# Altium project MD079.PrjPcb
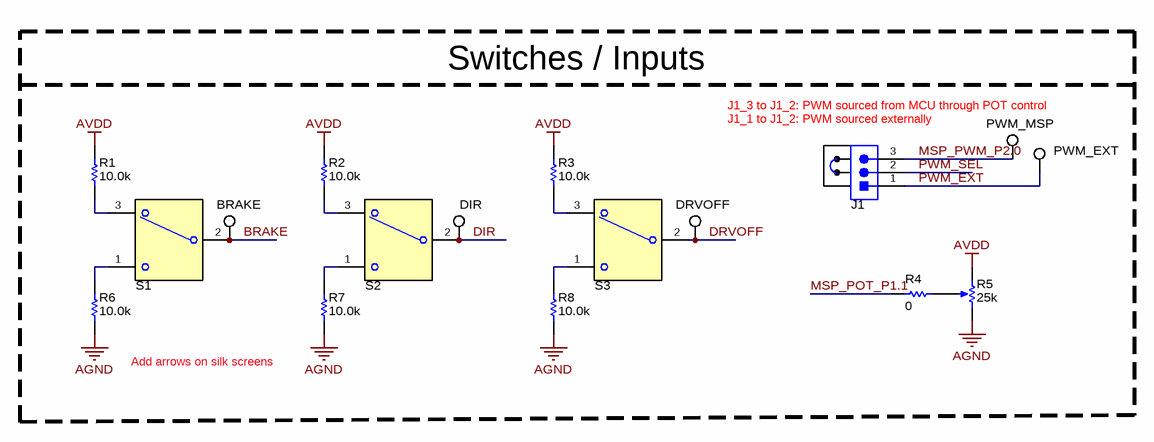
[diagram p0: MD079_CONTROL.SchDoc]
CopyrightYear: 2023; PCB_Layout: Hong Ze Khor; PCB_Rev: A; PRJ_Customer: Public Release; PRJ_Engineer: Hong Ze Khor; PRJ_Number: MD079; PRJ_Title: MCT8315ZEVM; ProjectVariant: EVM_Orderable; SCH_Rev: A; TechSupport: http://www.ti.com/support; TID: N/A
5 sheets, 172 parts. Net scope: global (net labels, ports and power ports of the same name join across sheets).
Board file: MD079.PcbDoc
Sheets:
  MD079_CONTROL.SchDoc
  MD079_DRIVER.SchDoc
  MD079_HARDWARE.SchDoc
  MD079_INTERFACE.SchDoc
  MD079_POWER_AND_CONNECTORS.SchDoc

## Sheet MD079_CONTROL.SchDoc
size 431 x 279 mm; Date: Not shown in title block; ApprovedBy: Not shown in title block; CheckedBy: Not shown in title block; Author: Not shown in title block; CompanyName: Not shown in title block; Engineer: Not shown in title block; Organization: Not shown in title block; Address1: Not shown in title block; Address2: Not shown in title block; Address3: Not shown in title block; Address4: Not shown in title block; DocumentNumber: 1; Revision: Use project parameter SCH_Rev; SheetNumber: 2; SheetTotal: 5; PageSetup: Record=PageOptions¦CenterHorizontal=True¦CenterVertical=True¦PrintScale=1.00¦XCorrection=1.00¦YCorrection=1.00¦PrintKind=0¦BorderSize=5000000¦LeftOffset=0¦BottomOffset=0¦Orientation=2¦PaperLength=1000¦PaperWidth=1000¦Scale=100¦PaperSource=15¦PrintQuality=600¦MediaType=1¦DitherType=10¦PaperKind=Letter¦PrintScaleMode=1

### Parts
J1  Header_3x1  [PBC03SAAN]  (value not drawn)
R1  ValueDisplayed: 10.0k  [0603]  (hidden comment: RC0603FR-0710KL)
R2  ValueDisplayed: 10.0k  [0603]  (hidden comment: RC0603FR-0710KL)
R3  ValueDisplayed: 10.0k  [0603]  (hidden comment: RC0603FR-0710KL)
R4  ValueDisplayed: 0  [0603L]  (hidden comment: ERJ-3GEY0R00V)
R5  value 25k  [Bourns_3352T]  (hidden comment: 3352T-1-253LF)
R6  ValueDisplayed: 10.0k  [0603]  (hidden comment: RC0603FR-0710KL)
R7  ValueDisplayed: 10.0k  [0603]  (hidden comment: RC0603FR-0710KL)
R8  ValueDisplayed: 10.0k  [0603]  (hidden comment: RC0603FR-0710KL)
S1  SW_SPDT_COM2_1_3  [SW_B12AP]  (value not drawn)
S2  SW_SPDT_COM2_1_3  [SW_B12AP]  (value not drawn)
S3  SW_SPDT_COM2_1_3  [SW_B12AP]  (value not drawn)
SH-J1  SNT-100-BK-G  [SNT-100-BK-G]  (value not drawn)
TP1  PWM_MSP  [Keystone5002]
TP2  PWM_EXT  [Keystone5002]
TP3  BRAKE  [Keystone5002]
TP4  DIR  [Keystone5002]
TP5  DRVOFF  [Keystone5002]

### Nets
AGND: R5.3(CW) R6.1 R7.1 R8.1
AVDD: R1.2 R2.2 R3.2 R5.1(CCW)
BRAKE: S1.2(COM) TP3.1
DIR: S2.2(COM) TP4.1
DRVOFF: S3.2(COM) TP5.1
MSP_POT_P1.1: R4.1
MSP_PWM_P2.0: J1.3 TP1.1
PWM_EXT: J1.1 TP2.1
PWM_SEL: J1.2
NetR1_1: R1.1 S1.3
NetR2_1: R2.1 S2.3
NetR3_1: R3.1 S3.3
NetR4_2: R4.2 R5.2(WIPER)
NetR6_2: R6.2 S1.1
NetR7_2: R7.2 S2.1
NetR8_2: R8.2 S3.1

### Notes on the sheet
- Switches / Inputs
- J1_1 to J1_2: PWM sourced externally
- J1_3 to J1_2: PWM sourced from MCU through POT control
- Add arrows on silk screens

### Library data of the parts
J1 = CMP-0002334-1: Header, 100mil, 3x1, Gold, TH; Manufacturer: Sullins Connector Solutions; CNHeader: TRUE; CT: FALSE; Green_Lifecycle: Not Set; Green_REACh: Incomplete
R1-R3 R6-R8 = CMP-0022746-5: RES, 10.0 k, 1%, 0.1 W, 0603; Manufacturer: Yageo; Power_W: 100mW; TempCo: 100 ppm/C; Value_Code: 10k0; Value: 10.0k; EIA_Code: E96; Res_ohm: 10k; SizeX_mm: 1.6; SizeY_mm: 0.8; SizeZ_mm: 1; Value2: 0.1W; SizeArea_mm2: 1.28; AEC Qualified: N; VDC_V: 75V; AEC Category: Q200; SizeAreaWB_mm2: 4.68
R4 = CMP-0025874-4: RES, 0, 5%, 0.1 W, AEC-Q200 Grade 0, 0603; Manufacturer: Panasonic; Power_W: 100mW; TempCo: 600 ppm/C; Value_Code: 0000; Value: 0; EIA_Code: E24; SizeX_mm: 1.6; SizeY_mm: 0.8; SizeZ_mm: 1; Value2: 0.1W; SizeArea_mm2: 1.28; AEC Qualified: Y; VDC_V: 50V; AEC Category: Q200; SizeAreaWB_mm2: 4.68
R5 = CMP-0001776-2: Trimmer Potentiometer, 25kohm, 0.5W, TH; Manufacturer: Bourns
S1-S3 = CMP-0002155-2: SWITCH TOGGLE SPDT 0.4VA 28V; PartNumber: B12AP; Manufacturer: NKK Switches; SwitchFunction: On-On; PositionCount: 2; CurrentRating_mA: 100A
SH-J1 = CMP-0003623-3: Shunt, 100mil, Gold plated, Black; Alternate PartNumber: 969102-0000-DA; Manufacturer: Samtec; Alternate Manufacturer: 3M; Value: 1x2
TP1-TP5 = CMP-0055139-2: Test Point, Miniature, White, TH; Manufacturer: Keystone Electronics; CNHeader: FALSE; Green_Lifecycle: Active; Green_REACh: Passed; ContactFinish: Silver; CT: TRUE

## Sheet MD079_DRIVER.SchDoc
size 431 x 279 mm; Date: Not shown in title block; ApprovedBy: Not shown in title block; CheckedBy: Not shown in title block; Author: Not shown in title block; CompanyName: Not shown in title block; Engineer: Not shown in title block; Organization: Not shown in title block; Address1: Not shown in title block; Address2: Not shown in title block; Address3: Not shown in title block; Address4: Not shown in title block; DocumentNumber: 2; Revision: Use project parameter SCH_Rev; SheetNumber: 3; SheetTotal: 5; PageSetup: Record=PageOptions¦CenterHorizontal=True¦CenterVertical=True¦PrintScale=1.00¦XCorrection=1.00¦YCorrection=1.00¦PrintKind=0¦BorderSize=5000000¦LeftOffset=0¦BottomOffset=0¦Orientation=2¦PaperLength=1000¦PaperWidth=1000¦Scale=100¦PaperSource=15¦PrintQuality=600¦MediaType=1¦DitherType=10¦PaperKind=Letter¦PrintScaleMode=1
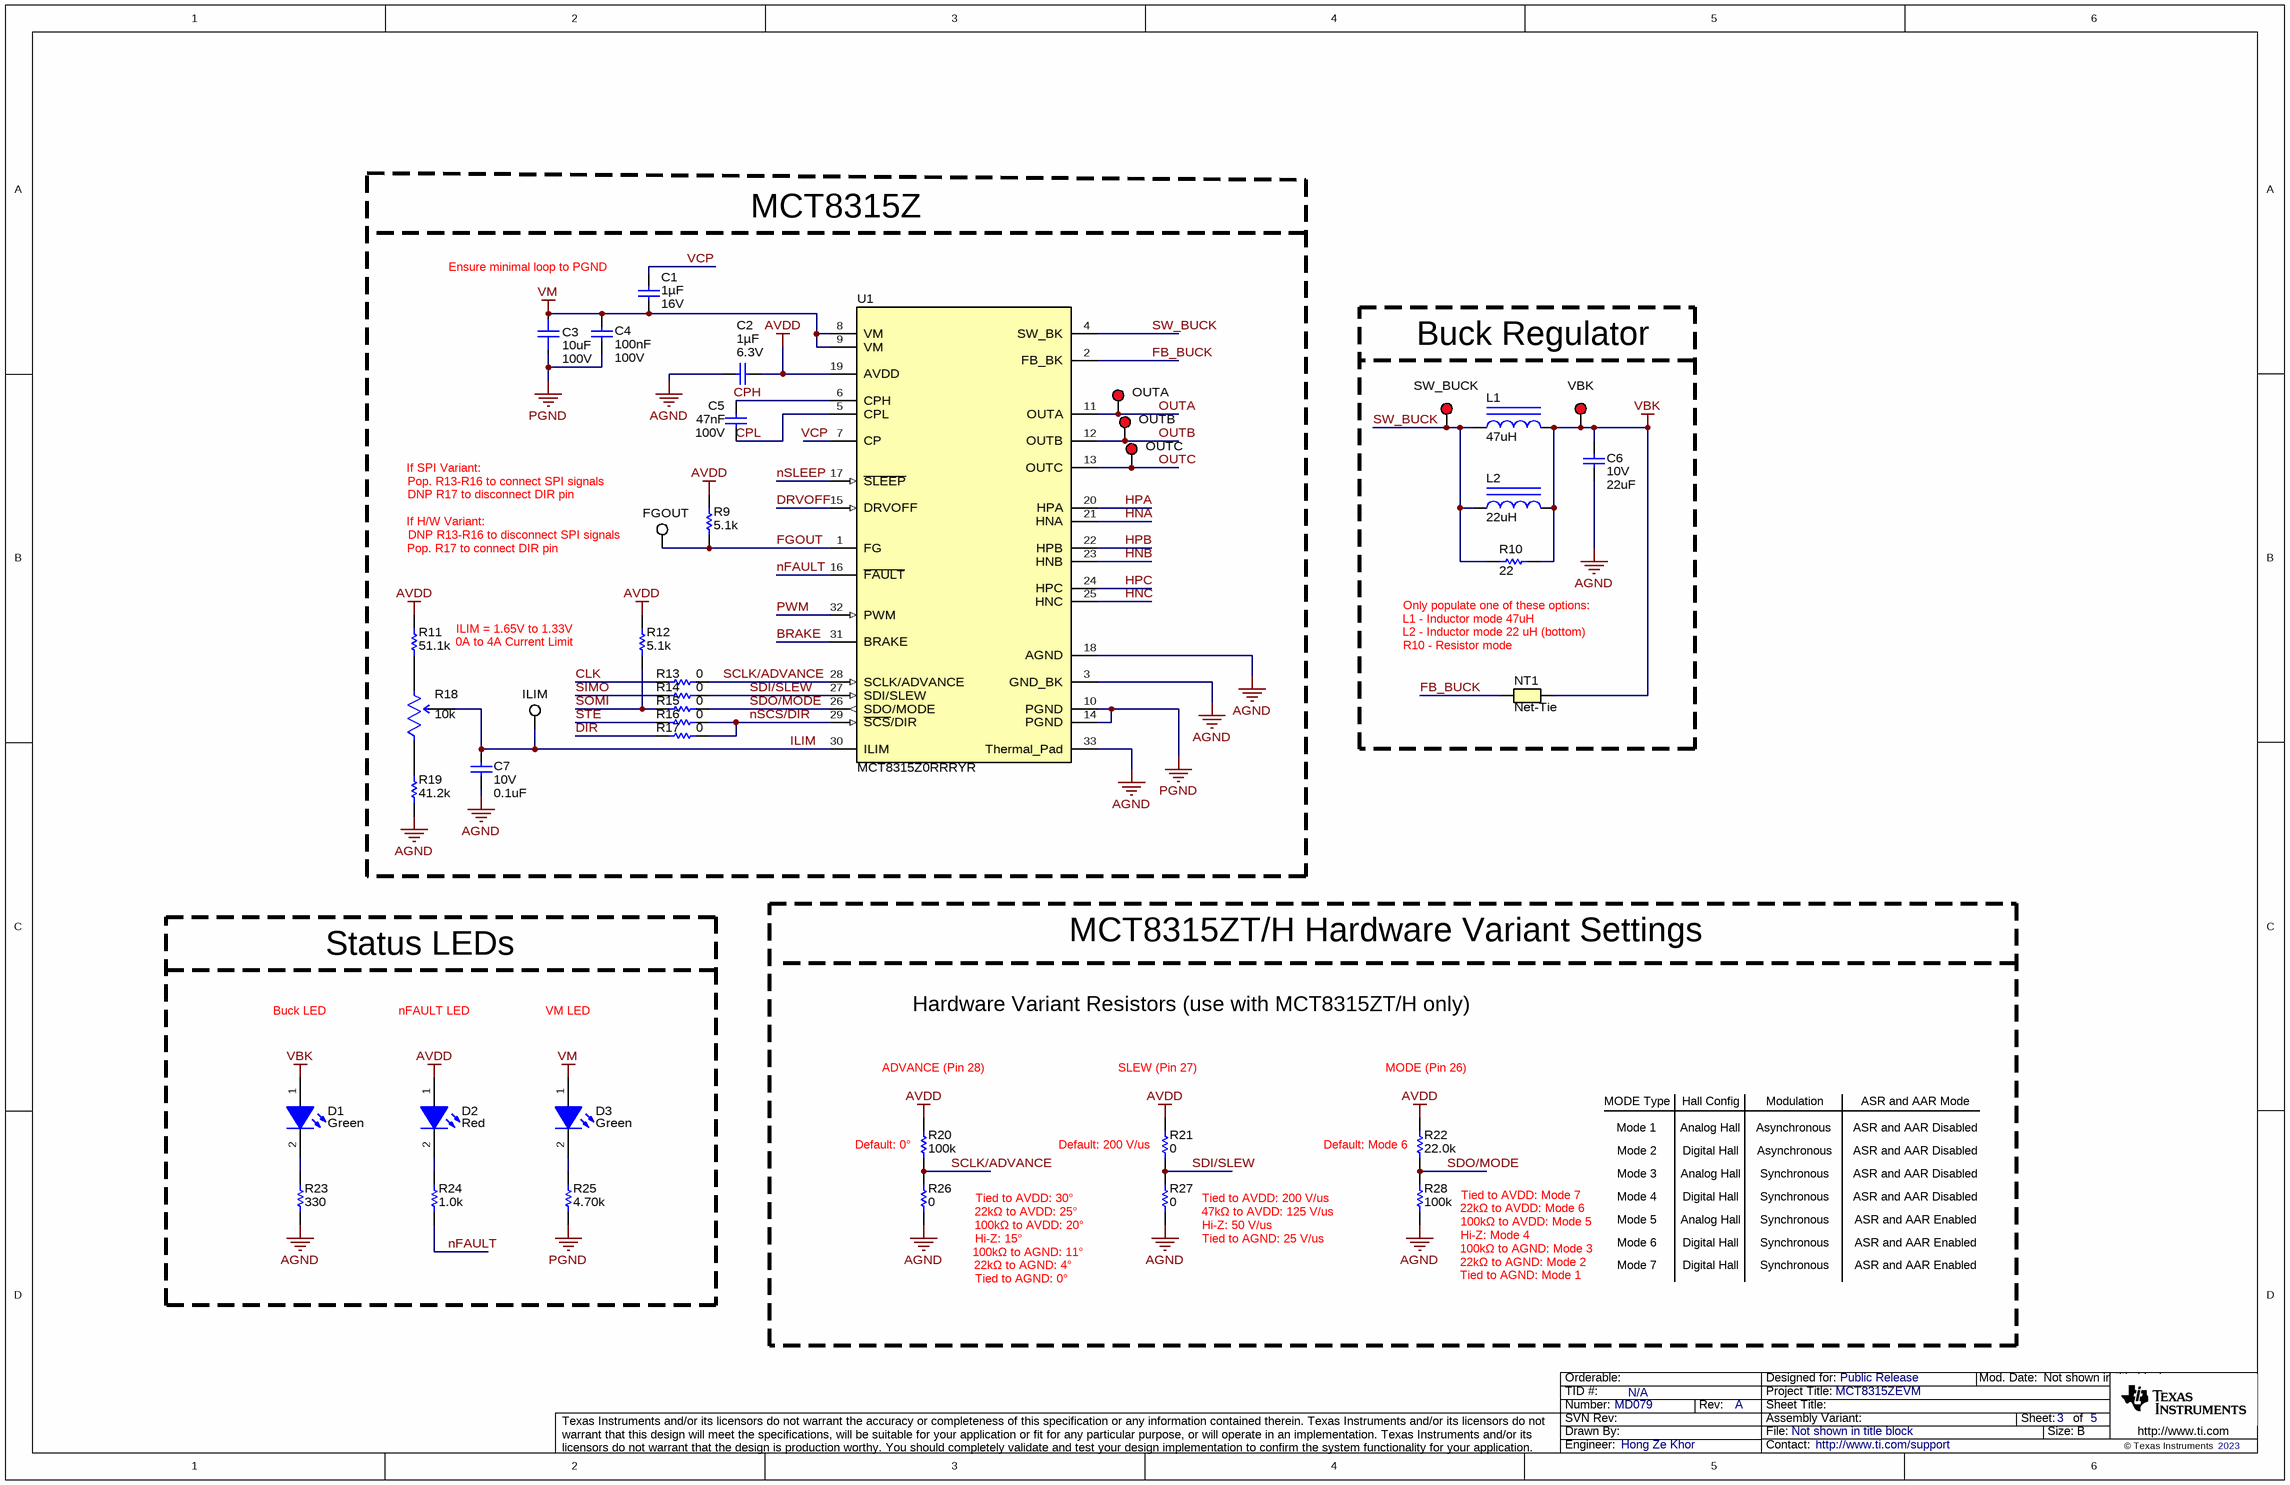
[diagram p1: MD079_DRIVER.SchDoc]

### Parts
C1  ValueDisplayed: 1µF  VDC_V: 16V  [0603]  (hidden comment: 0603YD105KAT2A)
C2  Cap_F: 1µF  VDC_V: 6.3V  [0603L]  (hidden comment: C0603C105K9RACAUTO)
C3  ValueDisplayed: 10uF  VDC_V: 100V  [FP-C3216X6S2A106K160AC_1206-MFG]  (hidden comment: C3216X6S2A106K160AC)
C4  Cap_F: 100nF  VDC_V: 100V  [0603]  (hidden comment: GCJ188R72A104KA01D)
C5  Cap_F: 47nF  VDC_V: 100V  [0805_HV]  (hidden comment: C2012X7R2A473K125AA)
C6  VDC_V: 10V  ValueDisplayed: 22uF  [1206_180L]  (hidden comment: GRM31CR71A226KE15L)
C7  VDC_V: 10V  ValueDisplayed: 0.1uF  [0402]  (hidden comment: C1005X5R1A104K050BA)
D1  value Green  [LTST-C170KGKT_Green]  (hidden comment: LTST-C170KGKT)
D2  value Red  [LED_LTST-C170_Red]  (hidden comment: LTST-C170KRKT)
D3  value Green  [LTST-C170KGKT_Green]  (hidden comment: LTST-C170KGKT)
L1  ValueDisplayed: 47uH  [WE-MAIA_3015]  (hidden comment: 78438335470)
L2  ValueDisplayed: 22uH  [WE-MAIA_3015]  (hidden comment: 78438335220)
NT1  Net-Tie  [Net-Tie_10mil]  (net tie, no BOM)
R9  ValueDisplayed: 5.1k  [0603L]  (hidden comment: CRCW06035K10JNEA)
R10  ValueDisplayed: 22  [2512]  (hidden comment: CRCW251222R0JNEGHP)
R11  ValueDisplayed: 51.1k  [0603]  (hidden comment: RC0603FR-0751K1L)
R12  ValueDisplayed: 5.1k  [0603L]  (hidden comment: CRCW06035K10JNEA)
R13  ValueDisplayed: 0  [0603L]  (hidden comment: ERJ-3GEY0R00V)
R14  ValueDisplayed: 0  [0603L]  (hidden comment: ERJ-3GEY0R00V)
R15  ValueDisplayed: 0  [0603L]  (hidden comment: ERJ-3GEY0R00V)
R16  ValueDisplayed: 0  [0603L]  (hidden comment: ERJ-3GEY0R00V)
R17  ValueDisplayed: 0  [0603L]  (hidden comment: ERJ-3GEY0R00V)
R18  value 10k  [Bourns_3352T]  (hidden comment: 3352T-1-103LF)
R19  ValueDisplayed: 41.2k  [0603]  (hidden comment: RC0603FR-0741K2L)
R20  ValueDisplayed: 100k  [0603L]  (hidden comment: ERA-3AEB104V)
R21  ValueDisplayed: 0  [0603L]  (hidden comment: ERJ-3GEY0R00V)
R22  ValueDisplayed: 22.0k  [0603L]  (hidden comment: ERJ-3EKF2202V)
R23  ValueDisplayed: 330  [0603L]  (hidden comment: RC0603FR-07330RL)
R24  ValueDisplayed: 1.0k  [0603L]  (hidden comment: RC0603JR-071KL)
R25  ValueDisplayed: 4.70k  [0603L]  (hidden comment: RT0603BRD074K7L)
R26  ValueDisplayed: 0  [0603L]  (hidden comment: ERJ-3GEY0R00V)
R27  ValueDisplayed: 0  [0603L]  (hidden comment: ERJ-3GEY0R00V)
R28  ValueDisplayed: 100k  [0603L]  (hidden comment: ERA-3AEB104V)
TP6  OUTA  [Keystone5000]
TP7  SW_BUCK  [Keystone5000]
TP8  VBK  [Keystone5000]
TP9  OUTB  [Keystone5000]
TP10  OUTC  [Keystone5000]
TP11  FGOUT  [Keystone5002]
TP12  ILIM  [Keystone5002]
U1  MCT8315Z0RRRYR  [RRY0032A-MFG]

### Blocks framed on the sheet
MCT8315Z: C1-C5 C7 R9 R11-R19 TP6 TP9-TP12 U1
Buck Regulator: C6 L1 L2 NT1 R10 TP7 TP8
MCT8315ZT/H Hardware Variant Settings: R20-R22 R26-R28
Status LEDs: D1-D3 R23-R25

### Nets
AGND: C2.1 C6.2 C7.2 R19.1 R23.1 R26.1 R27.1 R28.1 U1.3(GND_BK) U1.18(AGND) U1.33(Thermal_Pad)
AVDD: C2.2 D2.1(A) R9.2 R11.2 R12.2 R20.2 R21.2 R22.2 U1.19(AVDD)
PGND: C3.1 C4.2 R25.1 U1.10(PGND) U1.14(PGND)
VBK: C6.1 D1.1(A) L1.2 L2.2 NT1.2 R10.2 TP8.1
VM: C1.2 C3.2 C4.1 D3.1(A) U1.8(VM) U1.9(VM)
BRAKE: U1.31(BRAKE)
CLK: R13.1
CPH: C5.1 U1.6(CPH)
CPL: C5.2 U1.5(CPL)
DIR: R17.1
DRVOFF: U1.15(DRVOFF)
FB_BUCK: NT1.1 U1.2(FB_BK)
FGOUT: R9.1 TP11.1 U1.1(FG)
HNA: U1.21(HNA)
HNB: U1.23(HNB)
HNC: U1.25(HNC)
HPA: U1.20(HPA)
HPB: U1.22(HPB)
HPC: U1.24(HPC)
ILIM: C7.1 R18.2(WIPER) TP12.1 U1.30(ILIM)
nFAULT: R24.1 U1.16(~{FAULT})
nSCS/DIR: R16.2 R17.2 U1.29(~{SCS}/DIR)
nSLEEP: U1.17(~{SLEEP})
OUTA: TP6.1 U1.11(OUTA)
OUTB: TP9.1 U1.12(OUTB)
OUTC: TP10.1 U1.13(OUTC)
PWM: U1.32(PWM)
SCLK/ADVANCE: R13.2 R20.1 R26.2 U1.28(SCLK/ADVANCE)
SDI/SLEW: R14.2 R21.1 R27.2 U1.27(SDI/SLEW)
SDO/MODE: R15.2 R22.1 R28.2 U1.26(SDO/MODE)
SIMO: R14.1
SOMI: R12.1 R15.1
STE: R16.1
SW_BUCK: L1.1 L2.1 R10.1 TP7.1 U1.4(SW_BK)
VCP: C1.1 U1.7(CP)
NetD1_2: D1.2(K) R23.2
NetD2_2: D2.2(K) R24.2
NetD3_2: D3.2(K) R25.2
NetR11_1: R11.1 R18.3(CW)
NetR18_1: R18.1(CCW) R19.2

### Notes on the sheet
- Ensure minimal loop to PGND
- If SPI Variant:
- DNP R17 to disconnect DIR pin
- Pop. R13-R16 to connect SPI signals
- If H/W Variant:
- Pop. R17 to connect DIR pin
- (near TP11) DNP R13-R16 to disconnect SPI signals
- (near R11) ILIM = 1.65V to 1.33V
- L1 - Inductor mode 47uH
- L2 - Inductor mode 22 uH (bottom)
- (near R10) Only populate one of these options:
- 0A to 4A Current Limit
- (near NT1) R10 - Resistor mode
- Buck LED
- nFAULT LED
- VM LED
- Hardware Variant Resistors (use with MCT8315ZT/H only)
- ADVANCE (Pin 28)
- SLEW (Pin 27)
- MODE (Pin 26)
- MODE Type
- Hall Config
- Modulation
- ASR and AAR Mode
- (near R20) Default: 0°
- (near R21) Default: 200 V/us
- (near R22) Default: Mode 6
- Mode 1
- Mode 2
- Mode 3
- Analog Hall
- Digital Hall
- Asynchronous
- Synchronous
- ASR and AAR Disabled
- (near R26) Hi-Z: 15°
- Tied to AVDD: 30°
- 22kΩ to AVDD: 25°
- 100kΩ to AVDD: 20°
- (near R27) Hi-Z: 50 V/us
- (near R27) Tied to AGND: 25 V/us
- Tied to AVDD: 200 V/us
- (near R27) 47kΩ to AVDD: 125 V/us
- (near R28) Hi-Z: Mode 4
- Tied to AVDD: Mode 7
- 22kΩ to AVDD: Mode 6
- (near R28) 100kΩ to AVDD: Mode 5
- Mode 4
- Mode 6
- Mode 5
- ASR and AAR Enabled
- Tied to AGND: 0°
- 22kΩ to AGND: 4°
- 100kΩ to AGND: 11°
- Tied to AGND: Mode 1
- 22kΩ to AGND: Mode 2
- 100kΩ to AGND: Mode 3
- Mode 7

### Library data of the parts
C1 = CMP-0860183-1: CAP, CERM, 1 µF, 16 V,+/- 10%, X5R, 0603; Manufacturer: AVX; SizeArea_mm2: 1.28; U/M: EA; TaMax_C: 85°C; Polarized: N; Value: 1uF; AEC Category: Q200; SizeX_mm: 1.6; SizeAreaWB_mm2: 4.68; TaMin_C: -55°C; SizeZ_mm: 1; SizeY_mm: 0.8
C2 = CMP-0086190-1: CAP, CERM, 1 µF, 6.3 V,+/- 10%, X7R, AEC-Q200 Grade 1, 0603; Manufacturer: Kemet; SizeArea_mm2: 1.28; Cap_Case: 0603; SizeY_mm: 0.8; AEC Category: Q200; AEC Qualified: Y; TaMax_C: 125°C; SizeZ_mm: 1; SizeX_mm: 1.6; Polarized: N; Value: 1uF; SizeAreaWB_mm2: 4.68; TaMin_C: -55°C; U/M: EA
C3 = CMP-0098402-1: 10 µF ±10% 100V Ceramic Capacitor X6S 1206 (3216 Metric); Manufacturer: TDK; AEC Qualified: No; Cap_F: 10µF; SizeZ_mm: 1.9mm; TempCo: 22%; Value: 10µF
C4 = CMP-0064935-4: CAP, CERM, 0.1 uF, 100 V,+/- 10%, X7R, AEC-Q200 Grade 1, 0603; Manufacturer: MuRata; TaMin_C: -55°C; Polarized: N; SizeAreaWB_mm2: 4.68; Value1: Unknown; U/M: EA; Value: 0.1uF; TaMax_C: 125°C; SizeZ_mm: 1; SizeX_mm: 1.6; SizeY_mm: 0.8; SizeArea_mm2: 1.28; AEC Qualified: Y; AEC Category: Q200
C5 = CMP-0007887-2: CAP, CERM, 0.047 uF, 100 V, +/- 10%, X7R, 0805; Manufacturer: TDK; TaMin_C: -55°C; ESR_ohm: 0.049089; Polarized: N; SizeAreaWB_mm2: 6.75; Value1: 0.049089 ohm; U/M: EA; TaMax_C: 125°C; SizeZ_mm: 1.45; SizeX_mm: 2; SizeY_mm: 1.25; Cap_Case: 0805; SizeArea_mm2: 2.5; IRMS_A: 9.63171dA; AEC Category: Q200
C6 = CMP-0008959-2: CAP, CERM, 22 uF, 10 V, +/- 10%, X7R, 1206; Manufacturer: MuRata; TaMin_C: -55°C; Polarized: N; SizeAreaWB_mm2: 10.92; Value1: Unknown; U/M: EA; Value: 22uF; TaMax_C: 125°C; SizeZ_mm: 1.8; SizeX_mm: 3.2; SizeY_mm: 1.6; Cap_Case: 1206; SizeArea_mm2: 5.12; Cap_F: 22µF; AEC Category: Q200
C7 = CMP-0006259-2: CAP, CERM, 0.1 uF, 10 V, +/- 10%, X5R, 0402; Manufacturer: TDK; TaMin_C: -55°C; Polarized: N; SizeAreaWB_mm2: 3; Value1: Unknown; U/M: EA; Value: 0.1uF; TaMax_C: 85°C; SizeZ_mm: 0.6; SizeX_mm: 1; SizeY_mm: 0.5; Cap_F: 100nF; AEC Category: Q200
D1 D3 = CMP-0002888-2: LED, Green, SMD; Manufacturer: Lite-On; Io_A: 20mA; Value1: W; Vf_V: 2V; Type: AlInGaP
D2 = CMP-0002829-3: LED, Red, SMD; Manufacturer: Lite-On; Io_A: 20mA; SizeAreaWB_mm2: 6.75; Value1: W; SizeZ_mm: 1.2; SizeX_mm: 2; SizeY_mm: 1.25; Vf_V: 2V; SizeArea_mm2: 2.5; Type: AlInGaP
L1 = CMP-0064683-2: Inductor, Shielded, Powdered Iron, 47 uH, 0.39 A, 2.3 ohm, AEC-Q200 Grade 1, SMD; Manufacturer: Wurth Elektronik; Isat: 1.18A @ 20% inductance drop; Irms: 0.39A @ 40C rise; SizeAreaWB_mm2: 16; DCR_ohm: 2.3; Value1: 2.3 ohm; Value: 47uH; Imax_A: 390mA; SizeZ_mm: 1.5; SizeX_mm: 3; Value2: 0.39A; SizeArea_mm2: 9; Ind_H: 47µH; AEC Qualified: Y; AEC Grade: 1; AEC Category: Q200
L2 = CMP-0064681-2: Inductor, Shielded, Powdered Iron, 22 uH, 0.6 A, 1.04 ohm, AEC-Q200 Grade 1, SMD; Manufacturer: Wurth Elektronik; Isat: 1.6A @ 20% inductance drop; Irms: 0.6A @ 40C rise; SizeAreaWB_mm2: 16; DCR_ohm: 1.04; Value: 22uH; Imax_A: 600mA; SizeZ_mm: 1.5; SizeX_mm: 3; Value2: 0.6A; SizeArea_mm2: 9; Ind_H: 22µH; AEC Qualified: Y; AEC Grade: 1; AEC Category: Q200
NT1 = CMP-0078142-6: Single point connection between nets.
R9 R12 = CMP-0025830-4: RES, 5.1 k, 5%, 0.1 W, AEC-Q200 Grade 0, 0603; Manufacturer: Vishay-Dale; Power_W: 100mW; TempCo: 200 ppm/C; Value_Code: 5k10; Value: 5.1k; EIA_Code: E24; SizeX_mm: 1.6; SizeY_mm: 0.8; SizeZ_mm: 1; Value2: 0.1W; SizeArea_mm2: 1.28; AEC Qualified: Y; VDC_V: 75V; AEC Category: Q200; AEC Grade: 0
R10 = CMP-0015919-3: RES, 22, 5%, 1.5 W, AEC-Q200 Grade 0, 2512; Manufacturer: Vishay-Dale; Power_W: 1.5W; TempCo: 200 ppm/C; Value_Code: 22R0; Value: 22; EIA_Code: E24; SizeX_mm: 6.3; SizeY_mm: 3.2; SizeZ_mm: 0.71; SizeArea_mm2: 20.16; AEC Qualified: Y; VDC_V: 500V; AEC Category: Q200; AEC Grade: 0
R11 = CMP-0023166-5: RES, 51.1 k, 1%, 0.1 W, 0603; Manufacturer: Yageo; Power_W: 100mW; TempCo: 100 ppm/C; Value_Code: 51k1; Value: 51.1k; EIA_Code: E96; SizeX_mm: 1.6; SizeY_mm: 0.8; SizeZ_mm: 1; Value2: 0.1W; SizeArea_mm2: 1.28; AEC Qualified: N; VDC_V: 75V; AEC Category: Q200; SizeAreaWB_mm2: 4.68
R13-R17 R21 R26 R27 = CMP-0025874-4: as R4 on sheet MD079_CONTROL
R18 = CMP-0093882-3: 10 kOhms 0.5W, 1/2W Through Hole Thumbwheel Potentiometer Top Adjustment; Manufacturer: Bourns; Voltage: 250V; TempCo: 100ppm/°C; Standoff Height: 0.64mm; Res_ohm: 10kΩ; Tolerance_%: 20%; Power: 500mW; AEC Qualified: No; SizeZ_mm: 4.32mm
R19 = CMP-0023102-5: RES, 41.2 k, 1%, 0.1 W, 0603; Manufacturer: Yageo; Power_W: 100mW; TempCo: 100 ppm/C; Value_Code: 41k2; Value: 41.2k; EIA_Code: E96; SizeX_mm: 1.6; SizeY_mm: 0.8; SizeZ_mm: 1; Value2: 0.1W; SizeArea_mm2: 1.28; AEC Qualified: N; VDC_V: 75V; AEC Category: Q200; SizeAreaWB_mm2: 4.68
R20 R28 = CMP-0023363-3: RES, 100 k, 0.1%, 0.1 W, AEC-Q200 Grade 0, 0603; Manufacturer: Panasonic; Power_W: 100mW; TempCo: 25 ppm/C; U/M: EA; Value: 100k; EIA_Code: E192; SizeX_mm: 1.6; SizeY_mm: 0.8; SizeZ_mm: 1; Value2: 0.1W; SizeArea_mm2: 1.28; AEC Qualified: Y; VDC_V: 75V; AEC Grade: 0; AEC Category: Q200
R22 = CMP-0022692-3: RES, 22.0 k, 1%, 0.1 W, AEC-Q200 Grade 0, 0603; Manufacturer: Panasonic; Power_W: 100mW; TempCo: 100 ppm/C; Value_Code: 22k0; U/M: EA; Value: 22.0k; Res_ohm: 22k; SizeX_mm: 1.6; SizeY_mm: 0.8; SizeZ_mm: 1; Value2: 0.1W; SizeArea_mm2: 1.28; AEC Qualified: Y; VDC_V: 50V; AEC Grade: 0; AEC Category: Q200
R23 = CMP-0023033-5: RES, 330, 1%, 0.1 W, 0603; Manufacturer: Yageo; Power_W: 100mW; TempCo: 100 ppm/C; Value_Code: 330R; Value: 330; SizeX_mm: 1.6; SizeY_mm: 0.8; SizeZ_mm: 1; Value2: 0.1W; SizeArea_mm2: 1.28; AEC Qualified: N; VDC_V: 75V; AEC Category: Q200; SizeAreaWB_mm2: 4.68
R24 = CMP-0025899-5: RES, 1.0 k, 5%, 0.1 W, 0603; Manufacturer: Yageo; Power_W: 100mW; TempCo: 100 ppm/C; Value_Code: 1k00; Value: 1.0k; EIA_Code: E24; Res_ohm: 1k; SizeX_mm: 1.6; SizeY_mm: 0.8; SizeZ_mm: 1; Value2: 0.1W; SizeArea_mm2: 1.28; AEC Qualified: N; VDC_V: 75V; AEC Category: Q200; SizeAreaWB_mm2: 4.68
R25 = CMP-0024300-2: RES, 4.70 k, 0.1%, 0.1 W, 0603; Manufacturer: Yageo America; Power_W: 100mW; TempCo: 25 ppm/C; Value_Code: 4k70; U/M: EA; Value: 4.70k; EIA_Code: E192; Res_ohm: 4.7k; SizeX_mm: 1.6; SizeY_mm: 0.8; SizeZ_mm: 1; Value2: 0.1W; SizeArea_mm2: 1.28; VDC_V: 75V; AEC Category: Q200
TP6-TP10 = CMP-0055137-2: Test Point, Miniature, Red, TH; Manufacturer: Keystone Electronics; ContactFinish: Silver; CNHeader: FALSE; CT: TRUE; Green_Lifecycle: Active; Green_REACh: Passed
TP11 TP12 = CMP-0055139-2: as TP1 on sheet MD079_CONTROL
U1 = CMP-0098493-1: Manufacturer: Texas Instruments; SizeZ_mm: 0.8mm; Standoff Height: 0mm

## Sheet MD079_HARDWARE.SchDoc
size 431 x 279 mm; Date: Not shown in title block; ApprovedBy: Not shown in title block; CheckedBy: Not shown in title block; Author: Not shown in title block; CompanyName: Not shown in title block; Engineer: Not shown in title block; Organization: Not shown in title block; Address1: Not shown in title block; Address2: Not shown in title block; Address3: Not shown in title block; Address4: Not shown in title block; DocumentNumber: 3; Revision: Use project parameter SCH_Rev; SheetNumber: 5; SheetTotal: 5; PageSetup: Record=PageOptions¦CenterHorizontal=True¦CenterVertical=True¦PrintScale=1.00¦XCorrection=1.00¦YCorrection=1.00¦PrintKind=0¦BorderSize=5000000¦LeftOffset=0¦BottomOffset=0¦Orientation=2¦PaperLength=1000¦PaperWidth=1000¦Scale=100¦PaperSource=15¦PrintQuality=600¦MediaType=1¦DitherType=10¦PaperKind=Letter¦PrintScaleMode=1
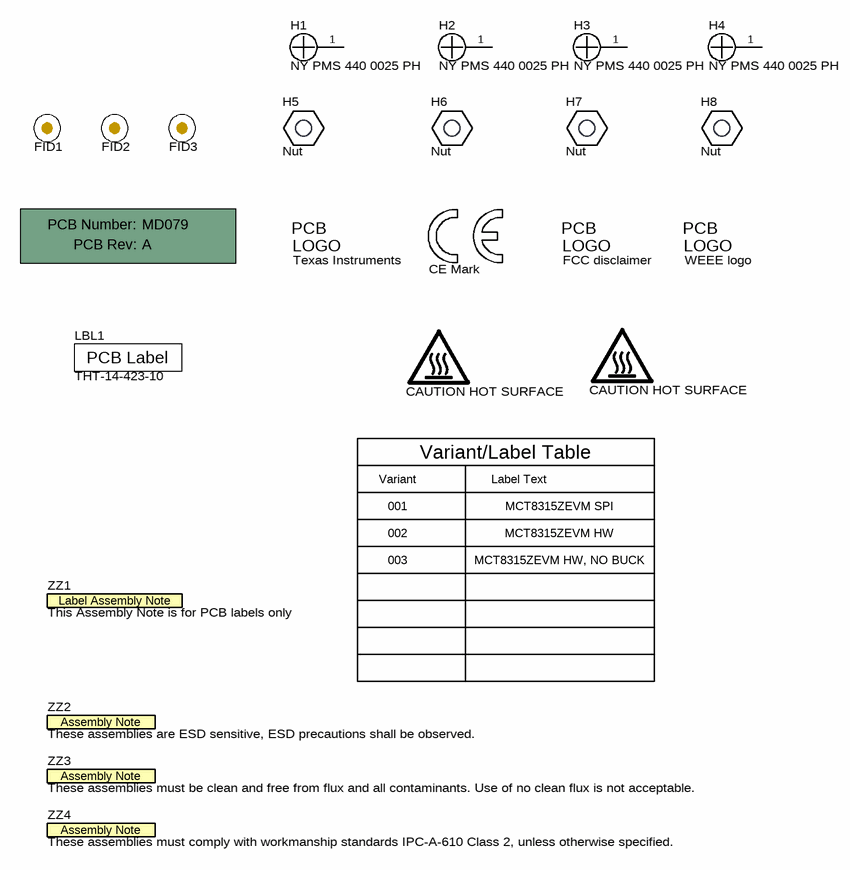
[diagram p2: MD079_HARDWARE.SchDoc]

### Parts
!PCB1  Printed Circuit Board  (value not drawn)  (mechanical)
FID1  Fiducial  [Fiducial10-20]  (value not drawn)
FID2  Fiducial  [Fiducial10-20]  (value not drawn)
FID3  Fiducial  [Fiducial10-20]  (value not drawn)
H1  NY PMS 440 0025 PH  [NY PMS 440 0025 PH]
H2  NY PMS 440 0025 PH  [NY PMS 440 0025 PH]
H3  NY PMS 440 0025 PH  [NY PMS 440 0025 PH]
H4  NY PMS 440 0025 PH  [NY PMS 440 0025 PH]
H5  Nut  [Keystone_1902C]
H6  Nut  [Keystone_1902C]
H7  Nut  [Keystone_1902C]
H8  Nut  [Keystone_1902C]
LBL1  THT-14-423-10  [Label_650x200]
Logo1  CE Mark  [CE_Mark_5mm]  (no BOM)
Logo2  Texas Instruments  [TI_Stacked_Overlay_Small]  (no BOM)
Logo3  FCC disclaimer  [FCC_disclaimer]  (no BOM)
Logo4  WEEE logo  [WEEE_Minimum]  (no BOM)
LOGO5  CAUTION HOT SURFACE  [IEC_HotSurface_Small]  (no BOM)
LOGO6  CAUTION HOT SURFACE  [IEC_HotSurface_Small]  (no BOM)
ZZ1  This Assembly Note is for PCB labels only  [AssemblyNoteLabel]  (no BOM)
ZZ2  These assemblies are ESD sensitive, ESD precautions shall be observed.  [AssemblyNote]  (no BOM)
ZZ3  These assemblies must be clean and free from flux and all contaminants. Use of no clean flux is not acceptable.  [AssemblyNote]  (no BOM)
ZZ4  These assemblies must comply with workmanship standards IPC-A-610 Class 2, unless otherwise specified.  [AssemblyNote]  (no BOM)

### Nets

Not connected (* = marked no-connect by the designer): H1 1; H2 1; H3 1; H4 1

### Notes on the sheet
- Variant
- Variant/Label Table
- Label Text
- 001
- 002
- MCT8315ZEVM SPI
- MCT8315ZEVM HW
- 003
- MCT8315ZEVM HW, NO BUCK

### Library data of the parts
!PCB1 = CMP-0003618-2: Manufacturer: Any; PartNumber: MD079
FID1-FID3 = CMP-0077181-1: Fiducial mark.  There is nothing to buy or mount.
H1-H4 = CMP-0003617-1: Machine Screw, Round, #4-40 x 1/4, Nylon, Philips panhead; Manufacturer: B&F Fastener Supply; CompType: Hardware
H5-H8 = CMP-0003610-1: Standoff, Hex, 0.5"L #4-40 Nylon; Manufacturer: Keystone; PartNumber: 1902C; CompType: Hardware
LBL1 = CMP-0003625-1: Manufacturer: Brady
Logo1 = CMP-0074844-1: SymbolCreator: a0412235
Logo2 = CMP-0074838-1: Texas Instrument Corporate Signature; SymbolCreator: a0412235; Lib Reference: TI_Logo; Library Reference: Logo
Logo3 = CMP-0074847-1: FCC_disclaimer; Library Reference: Logo
Logo4 = CMP-0074769-3: Manufacturer: Texas Instruments; CompType: IC; AEC Category: Q200
LOGO5 LOGO6 = CMP-0074837-2: IEC 61010-1 Hot Surface Warning; Manufacturer: Texas Instruments; SymbolCreator: a0412235; CompType: IC; AEC Category: Q200
ZZ1 = CMP-0003616-3
ZZ2 = CMP-0077236-1
ZZ3 = CMP-0077237-1
ZZ4 = CMP-0077238-1

## Sheet MD079_INTERFACE.SchDoc
size 431 x 279 mm; Date: Not shown in title block; ApprovedBy: Not shown in title block; CheckedBy: Not shown in title block; Author: Not shown in title block; CompanyName: Not shown in title block; Engineer: Not shown in title block; Organization: Not shown in title block; Address1: Not shown in title block; Address2: Not shown in title block; Address3: Not shown in title block; Address4: Not shown in title block; DocumentNumber: 4; Revision: Use project parameter SCH_Rev; SheetNumber: 1; SheetTotal: 5; PageSetup: Record=PageOptions¦CenterHorizontal=True¦CenterVertical=True¦PrintScale=1.00¦XCorrection=1.00¦YCorrection=1.00¦PrintKind=0¦BorderSize=5000000¦LeftOffset=0¦BottomOffset=0¦Orientation=2¦PaperLength=1000¦PaperWidth=1000¦Scale=100¦PaperSource=15¦PrintQuality=600¦MediaType=1¦DitherType=10¦PaperKind=Letter¦PrintScaleMode=1
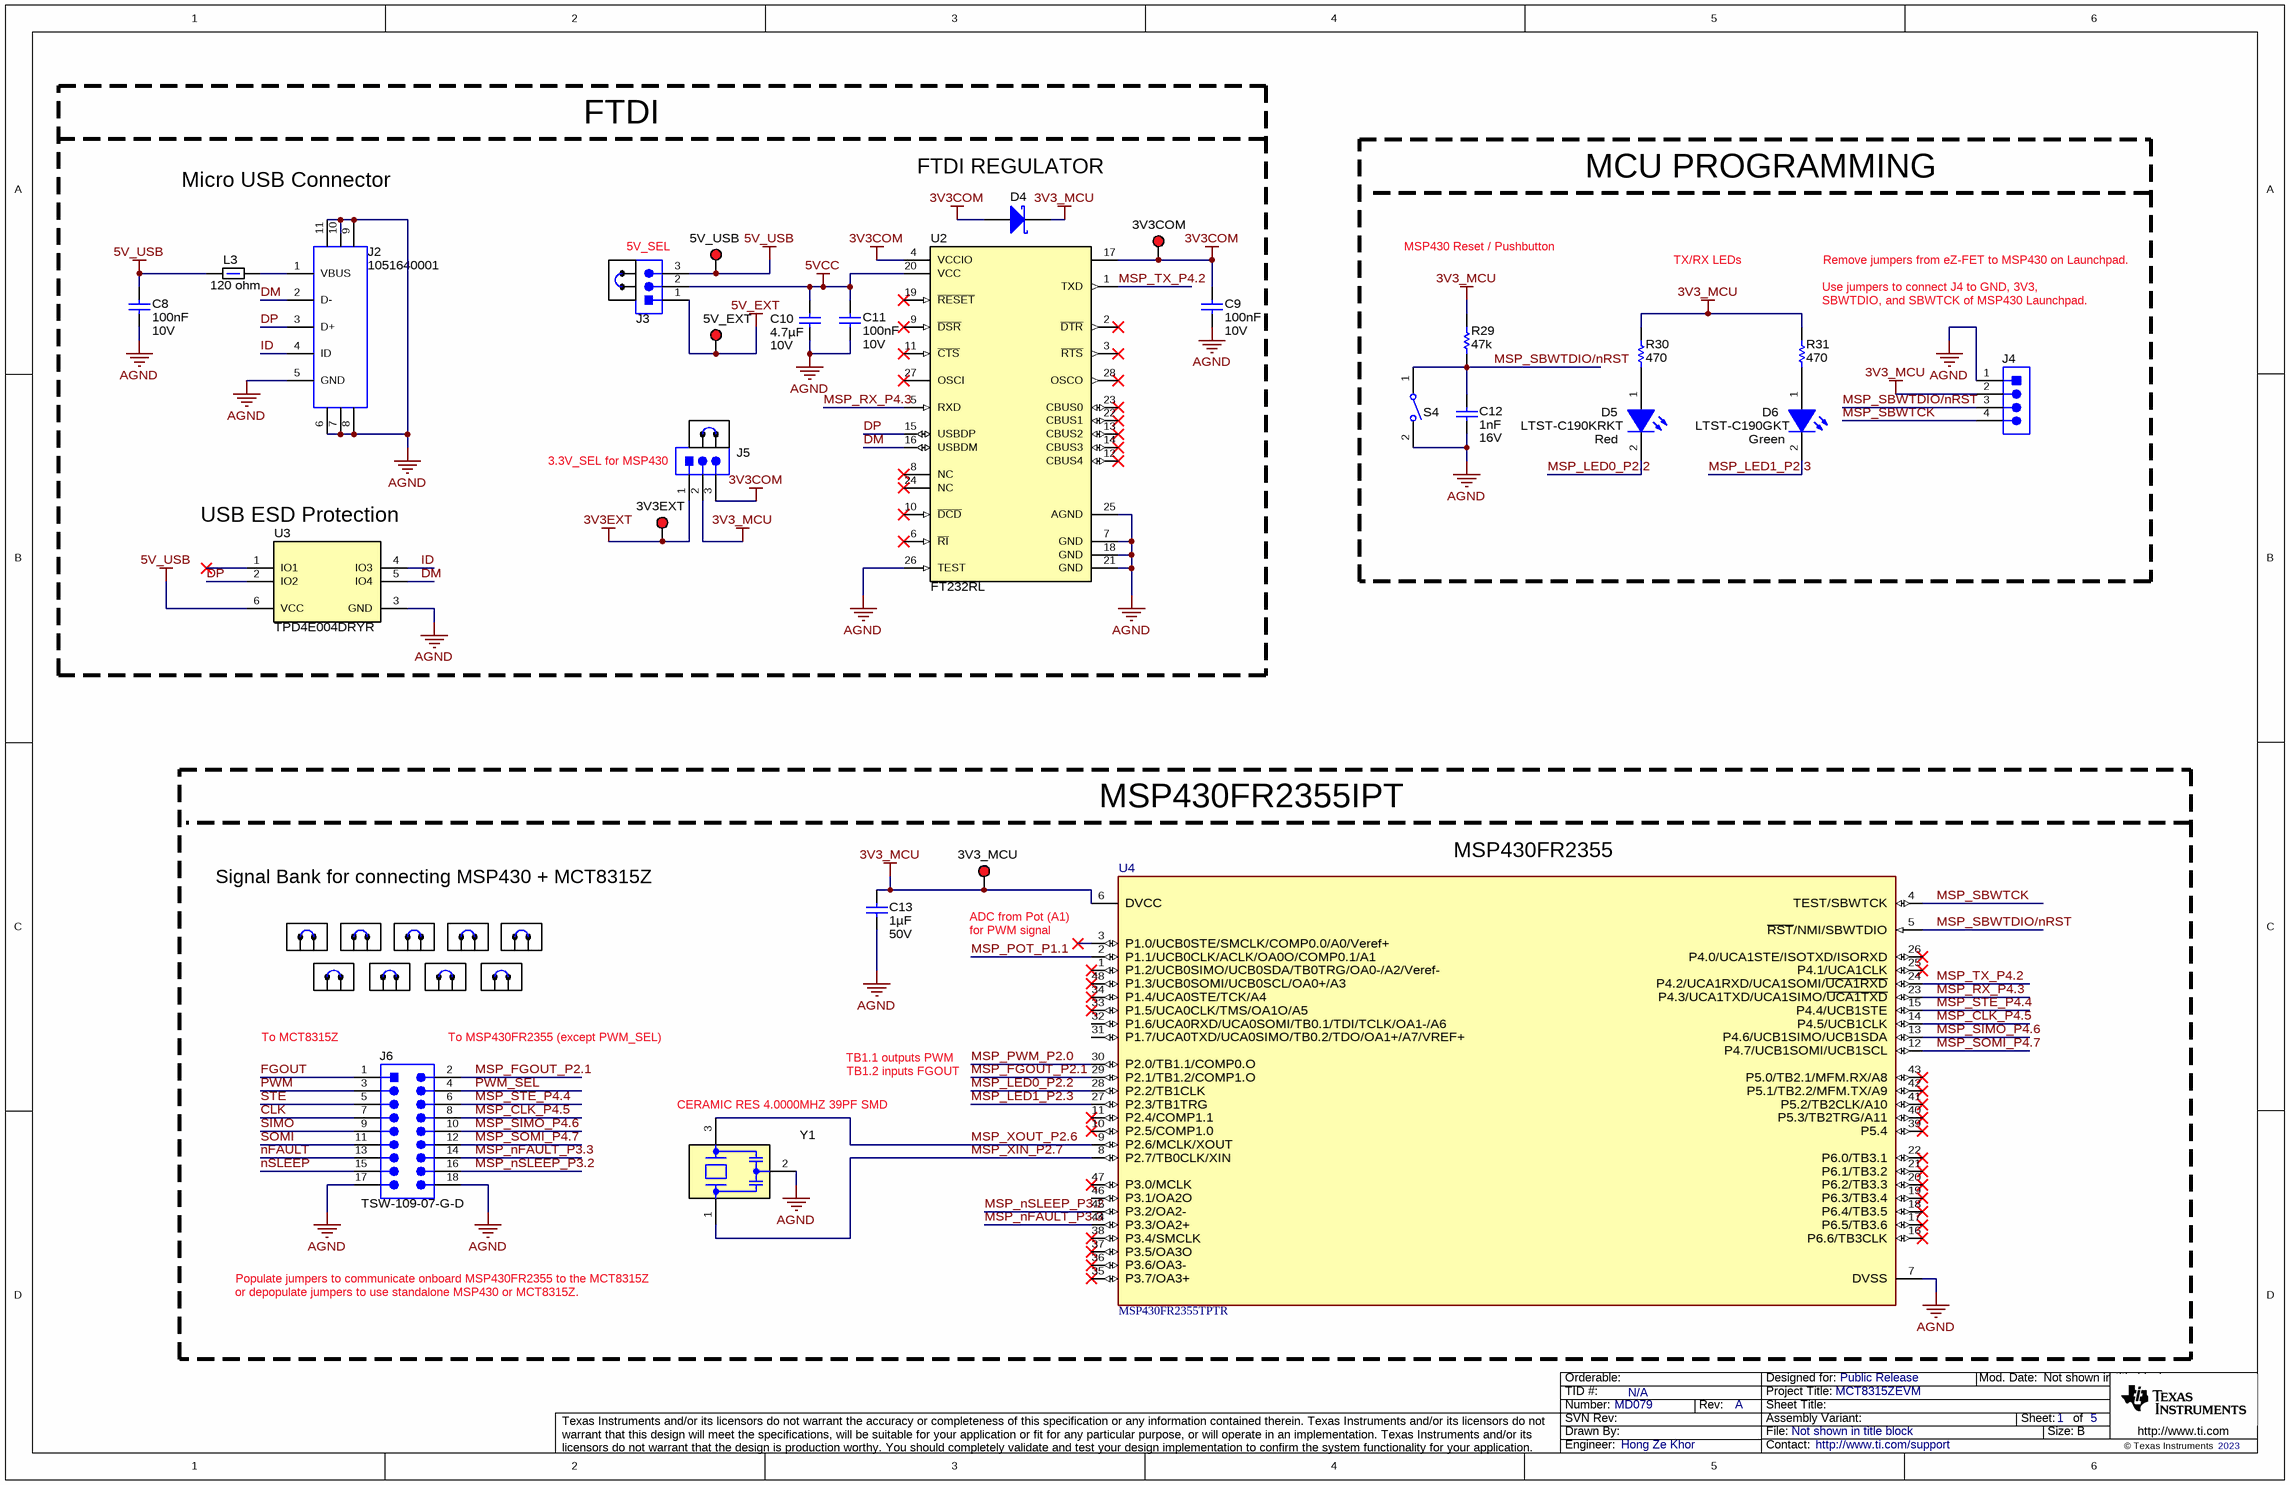
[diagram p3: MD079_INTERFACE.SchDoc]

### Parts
C8  Cap_F: 100nF  VDC_V: 10V  [0603L]  (hidden comment: C0603C104K8RACTU)
C9  Cap_F: 100nF  VDC_V: 10V  [0603]  (hidden comment: C0603C104K8RACTU)
C10  Cap_F: 4.7µF  VDC_V: 10V  [0603L]  (hidden comment: GRM188Z71A475ME15D)
C11  Cap_F: 100nF  VDC_V: 10V  [0603L]  (hidden comment: C0603C104K8RACTU)
C12  Cap_F: 1nF  VDC_V: 16V  [0603L]  (hidden comment: 885012206034)
C13  Cap_F: 1µF  VDC_V: 50V  [0805_HV]  (hidden comment: C0805C105K5RACTU)
D4  BAT165E6327HTSA1  [SOD-323]  (value not drawn)
D5  LTST-C190KRKT  value Red  [LED_LTST-C190_Red]
D6  LTST-C190GKT  value Green  [LED_LTST-C190]
J2  1051640001  [Molex_1051640001]
J3  Header_3x1  [PBC03SAAN]  (value not drawn)
J4  TSW-104-07-G-S  [TSW-104-07-G-S]  (value not drawn)
J5  Header_3x1  [PBC03SAAN]  (value not drawn)
J6  TSW-109-07-G-D  [Samtec_TSW-109-07-G-D]
L3  DCR_ohm: 120 ohm  [0603L]  (hidden comment: BLM18SG121TZ1D)
R29  ValueDisplayed: 47k  [0603L]  (hidden comment: RC0603JR-0747KL)
R30  ValueDisplayed: 470  [0603L]  (hidden comment: RC0603JR-07470RL)
R31  ValueDisplayed: 470  [0603L]  (hidden comment: RC0603JR-07470RL)
S4  SW_SPST-single  [SW_434121025816]  (value not drawn)
SH-J2  SNT-100-BK-G  [SNT-100-BK-G]  (value not drawn)
SH-J3  SNT-100-BK-G  [SNT-100-BK-G]  (value not drawn)
SH-J4  SNT-100-BK-G  [SNT-100-BK-G]  (value not drawn)
SH-J5  SNT-100-BK-G  [SNT-100-BK-G]  (value not drawn)
SH-J6  SNT-100-BK-G  [SNT-100-BK-G]  (value not drawn)
SH-J7  SNT-100-BK-G  [SNT-100-BK-G]  (value not drawn)
SH-J8  SNT-100-BK-G  [SNT-100-BK-G]  (value not drawn)
SH-J9  SNT-100-BK-G  [SNT-100-BK-G]  (value not drawn)
SH-J10  SNT-100-BK-G  [SNT-100-BK-G]  (value not drawn)
SH-J11  SNT-100-BK-G  [SNT-100-BK-G]  (value not drawn)
SH-J12  SNT-100-BK-G  [SNT-100-BK-G]  (value not drawn)
TP13  5V_EXT  [Keystone5000]
TP14  3V3EXT  [Keystone5000]
TP32  3V3COM  [Keystone5000]
TP33  5V_USB  [Keystone5000]
TP34  3V3_MCU  [Keystone5000]
U2  FT232RL  [SSOP28_N]
U3  TPD4E004DRYR  [DRY0006A]
U4  MSP430FR2355TPTR  [PT0048A-MFG]
Y1  CSTCR4M00G55B-R0  [Murata_CSTCR_G]  (value not drawn)

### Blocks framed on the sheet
FTDI: C8-C11 D4 J2 J3 J5 L3 SH-J2 SH-J3 TP13 TP14 TP32 TP33 U2 U3
MCU PROGRAMMING: C12 D5 D6 J4 R29-R31 S4
MSP430FR2355IPT: C13 J6 SH-J4-SH-J12 TP34 U4 Y1

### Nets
3V3_MCU: C13.1 D4.1(K) J4.2 J5.2 R29.2 R30.2 R31.2 TP34.1 U4.6(DVCC)
3V3COM: C9.1 D4.2(A) J5.3 TP32.1 U2.4(VCCIO) U2.17(3V3OUT)
3V3EXT: J5.1 TP14.1
5V_EXT: J3.1 TP13.1
5V_USB: C8.1 J3.3 L3.1 TP33.1 U3.6(VCC)
5VCC: C10.2 C11.1 J3.2 U2.20(VCC)
AGND: C8.2 C9.2 C10.1 C11.2 C12.2 C13.2 J2.5(GND) J2.6 J2.7 J2.8 J2.9 J2.10 J2.11 J4.1 J6.17 J6.18 S4.2 U2.7(GND) U2.18(GND) U2.21(GND) U2.25(AGND) U2.26(TEST) U3.3(GND) U4.7(DVSS) Y1.2(GND)
CLK: J6.7
DM: J2.2(D-) U2.16(USBDM) U3.5(IO4)
DP: J2.3(D+) U2.15(USBDP) U3.2(IO2)
FGOUT: J6.1
ID: J2.4(ID) U3.4(IO3)
MSP_CLK_P4.5: J6.8 U4.14(P4.5/UCB1CLK)
MSP_FGOUT_P2.1: J6.2 U4.29(P2.1/TB1.2/COMP1.O)
MSP_LED0_P2.2: D5.2(K) U4.28(P2.2/TB1CLK)
MSP_LED1_P2.3: D6.2(K) U4.27(P2.3/TB1TRG)
MSP_nFAULT_P3.3: J6.14 U4.44(P3.3/OA2+)
MSP_nSLEEP_P3.2: J6.16 U4.45(P3.2/OA2-)
MSP_POT_P1.1: U4.2(P1.1/UCB0CLK/ACLK/OA0O/COMP0.1/A1)
MSP_PWM_P2.0: U4.30(P2.0/TB1.1/COMP0.O)
MSP_RX_P4.3: U2.5(RXD) U4.23(P4.3/UCA1TXD/UCA1SIMO/~{UCA1TXD})
MSP_SBWTCK: J4.4 U4.4(TEST/SBWTCK)
MSP_SBWTDIO/nRST: C12.1 J4.3 R29.1 S4.1 U4.5(~{RST}/NMI/SBWTDIO)
MSP_SIMO_P4.6: J6.10 U4.13(P4.6/UCB1SIMO/UCB1SDA)
MSP_SOMI_P4.7: J6.12 U4.12(P4.7/UCB1SOMI/UCB1SCL)
MSP_STE_P4.4: J6.6 U4.15(P4.4/UCB1STE)
MSP_TX_P4.2: U2.1(TXD) U4.24(P4.2/UCA1RXD/UCA1SOMI/~{UCA1RXD})
MSP_XIN_P2.7: U4.8(P2.7/TB0CLK/XIN) Y1.1(In)
MSP_XOUT_P2.6: U4.9(P2.6/MCLK/XOUT) Y1.3(Out)
nFAULT: J6.13
nSLEEP: J6.15
PWM: J6.3
PWM_SEL: J6.4
SIMO: J6.9
SOMI: J6.11
STE: J6.5
NetD5_1: D5.1(A) R30.1
NetD6_1: D6.1(A) R31.1
NetJ2_1: J2.1(VBUS) L3.2

Not connected (* = marked no-connect by the designer): U2 2(~{DTR})* 3(~{RTS})* 6(~{RI})* 8(NC)* 9(~{DSR})* 10(~{DCD})* 11(~{CTS})* 12(CBUS4)* 13(CBUS2)* 14(CBUS3)* 19(~{RESET})* 22(CBUS1)* 23(CBUS0)* 24(NC)* 27(OSCI)* 28(OSCO)*; U3 1(IO1)*; U4 1(P1.2/UCB0SIMO/UCB0SDA/TB0TRG/OA0-/A2/Veref-)* 3(P1.0/UCB0STE/SMCLK/COMP0.0/A0/Veref+)* 10(P2.5/COMP1.0)* 11(P2.4/COMP1.1)* 16(P6.6/TB3CLK)* 17(P6.5/TB3.6)* 18(P6.4/TB3.5)* 19(P6.3/TB3.4)* 20(P6.2/TB3.3)* 21(P6.1/TB3.2)* 22(P6.0/TB3.1)* 25(P4.1/UCA1CLK)* 26(P4.0/UCA1STE/ISOTXD/ISORXD)* 31(P1.7/UCA0TXD/UCA0SIMO/TB0.2/TDO/OA1+/A7/VREF+) 32(P1.6/UCA0RXD/UCA0SOMI/TB0.1/TDI/TCLK/OA1-/A6) 33(P1.5/UCA0CLK/TMS/OA1O/A5)* 34(P1.4/UCA0STE/TCK/A4)* 35(P3.7/OA3+)* 36(P3.6/OA3-)* 37(P3.5/OA3O)* 38(P3.4/SMCLK)* 39(P5.4)* 40(P5.3/TB2TRG/A11)* 41(P5.2/TB2CLK/A10)* 42(P5.1/TB2.2/MFM.TX/A9)* 43(P5.0/TB2.1/MFM.RX/A8)* 46(P3.1/OA2O) 47(P3.0/MCLK)* 48(P1.3/UCB0SOMI/UCB0SCL/OA0+/A3)*

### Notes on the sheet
- (near D4) FTDI REGULATOR
- Micro USB Connector
- 5V_SEL
- MSP430 Reset / Pushbutton
- TX/RX LEDs
- (near R31) Use jumpers to connect J4 to GND, 3V3,
- SBWTDIO, and SBWTCK of MSP430 Launchpad.
- Remove jumpers from eZ-FET to MSP430 on Launchpad.
- (near J5) 3.3V_SEL for MSP430
- (near U3) USB ESD Protection
- Signal Bank for connecting MSP430 + MCT8315Z
- (near U4) MSP430FR2355
- for PWM signal
- ADC from Pot (A1)
- To MCT8315Z
- To MSP430FR2355 (except PWM_SEL)
- (near Y1) CERAMIC RES 4.0000MHZ 39PF SMD
- TB1.1 outputs PWM
- TB1.2 inputs FGOUT
- or depopulate jumpers to use standalone MSP430 or MCT8315Z.
- Populate jumpers to communicate onboard MSP430FR2355 to the MCT8315Z

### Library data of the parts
C8 C11 = CMP-0006862-5: CAP, CERM, 0.1 uF, 10 V, +/- 10%, X7R, 0603; Manufacturer: Kemet; TaMin_C: -55°C; Polarized: N; SizeAreaWB_mm2: 4.68; Value1: Unknown; U/M: EA; Value: 0.1uF; TaMax_C: 125°C; SizeZ_mm: 1; SizeX_mm: 1.6; SizeY_mm: 0.8; Cap_Case: 0603; SizeArea_mm2: 1.28; AEC Category: Q200
C9 = CMP-0006862-5: CAP, CERM, 0.1 uF, 10 V, +/- 10%, X7R, 0603; Manufacturer: Kemet; TaMin_C: -55°C; Polarized: N; SizeAreaWB_mm2: 4.68; Value1: Unknown; U/M: EA; Value: 0.1uF; TaMax_C: 125°C; SizeZ_mm: 1; SizeX_mm: 1.6; SizeY_mm: 0.8; SizeArea_mm2: 1.28; AEC Category: Q200
C10 = CMP-0007498-4: CAP, CERM, 4.7 uF, 10 V, +/- 20%, X7R, 0603; Manufacturer: MuRata; TaMin_C: -55°C; Polarized: N; SizeAreaWB_mm2: 4.68; Value1: Unknown; U/M: EA; Value: 4.7uF; TaMax_C: 125°C; SizeZ_mm: 1; SizeX_mm: 1.6; SizeY_mm: 0.8; Cap_Case: 0603; SizeArea_mm2: 1.28; AEC Category: Q200
C12 = CMP-0006826-4: CAP, CERM, 1000 pF, 16 V, +/- 10%, X7R, 0603; Manufacturer: Wurth Elektronik; TaMin_C: -55°C; Polarized: N; SizeAreaWB_mm2: 4.68; Value1: Unknown; U/M: EA; Value: 1000pF; TaMax_C: 125°C; SizeZ_mm: 1; SizeX_mm: 1.6; SizeY_mm: 0.8; Cap_Case: 0603; SizeArea_mm2: 1.28; AEC Category: Q200
C13 = CMP-0007730-2: CAP, CERM, 1 uF, 50 V, +/- 10%, X7R, 0805; Manufacturer: Kemet; TaMin_C: -55°C; Polarized: N; SizeAreaWB_mm2: 6.75; Value1: Unknown; U/M: EA; Value: 1uF; TaMax_C: 125°C; SizeZ_mm: 1.45; SizeX_mm: 2; SizeY_mm: 1.25; Cap_Case: 0805; SizeArea_mm2: 2.5; AEC Category: Q200
D4 = CMP-0028882-2: Diode, Schottky, 40 V, 0.75 A, AEC-Q101, SOD-323; Manufacturer: Infineon Technologies; Vf_V: 740mV; Value: 40V; Value1: 0.75A; Value2: 0.74V; Io_A: 750mA; TJmax_C: 150°C; AEC Category: Q101; AEC Qualified: Y; Green_Lifecycle: Not Set; Green_REACh: Incomplete; SizeArea_mm2: 3.645; SizeAreaWB_mm2: 8.695; SizeX_mm: 2.7; SizeY_mm: 1.35; SizeZ_mm: 1
D5 = CMP-0078131-2: LED, Red, SMD; Manufacturer: Lite-On; Type: AlInGaP; Ir_A: 10µA; Angle: 130; Power_TotalModule: 62.5mW; Value2: 2V; Green_Lifecycle: Not Set; Io_A: 20mA; Value1: .0625W; Green_REACh: Incomplete; Vr_V: 5V
D6 = CMP-0002827-3: LED, Green, SMD; Manufacturer: Lite-On; Power_TotalModule: 100mW; Value2: 2.1V; Io_A: 20mA; Value1: 0.1W
J2 = CMP-0055311-1: Receptacle, USB 2.0, Micro B, 5 Position, R/A, SMT; Manufacturer: Molex; CNHeader: FALSE; Current_A: 1.8A; Gender: Female; Voltage_V: 30V; Pitch_mm: 0.65; ContactFinish: Gold; CT: TRUE; Cert_UL: Y
J3 J5 = CMP-0002334-1: as J1 on sheet MD079_CONTROL
J4 = CMP-0075409-2: Header, 100mil, 4x1, Gold, TH; Manufacturer: Samtec; Pitch_mm: 2.54; Cert_VDE: N; Gender: Male; Cert_CSA: Y; Voltage_V: 550V; Green_REACh: Passed; Current_A: 6.3A; Green_Lifecycle: Active; Row_Count: 1
J6 = CMP-0075464-1: Header, 100mil, 9x2, Gold, TH; Manufacturer: Samtec; Pitch_mm: 2.54; Cert_VDE: N; Gender: Male; Cert_CSA: Y; Voltage_V: 550V; Green_REACh: Passed; Current_A: 6.3A; CT: False; Green_Lifecycle: Active; Row_Count: 2; CNHeader: True
L3 = CMP-0084877-1: Inductor, Ferrite Bead, Ferrite, 3 A, 120 ohm, AEC-Q200 Grade 1, SMD; Manufacturer: MuRata; SizeX_mm: 1.6; AEC Grade: 1; Value2: 3A; SizeY_mm: 0.8; SizeAreaWB_mm2: 4.68; SizeArea_mm2: 1.28; AEC Qualified: Y; AEC Category: Q200
R29 = CMP-0025925-5: RES, 47 k, 5%, 0.1 W, 0603; Manufacturer: Yageo; Power_W: 100mW; TempCo: 100 ppm/C; Value_Code: 47k0; Value: 47k; EIA_Code: E24; SizeX_mm: 1.6; SizeY_mm: 0.8; SizeZ_mm: 1; Value2: 0.1W; SizeArea_mm2: 1.28; AEC Qualified: N; VDC_V: 75V; AEC Category: Q200; SizeAreaWB_mm2: 4.68
R30 R31 = CMP-0025924-5: RES, 470, 5%, 0.1 W, 0603; Manufacturer: Yageo; Power_W: 100mW; TempCo: 100 ppm/C; Value_Code: 470R; Value: 470; EIA_Code: E24; SizeX_mm: 1.6; SizeY_mm: 0.8; SizeZ_mm: 1; Value2: 0.1W; SizeArea_mm2: 1.28; AEC Qualified: N; VDC_V: 75V; AEC Category: Q200; SizeAreaWB_mm2: 4.68
S4 = CMP-0002196-2: Switch, Tactile, SPST, 12 V, SMD; PartNumber: 434121025816; Manufacturer: Wurth Elektronik; VDC_V: 12V; SwitchFunction: Off-On; PositionCount: 1; CurrentRating_mA: 50A
SH-J2-SH-J12 = CMP-0003623-3: as SH-J1 on sheet MD079_CONTROL
TP13 TP14 TP32-TP34 = CMP-0055137-2: as TP6 on sheet MD079_DRIVER
U2 = CMP-0004774-1: USB to Serial UART, SSOP28; Manufacturer: FTDI
U3 = CMP-0043115-3: 4-Channel ESD Protection Array for High-Speed Data Interfaces, DRY0006A (USON-6); Manufacturer: Texas Instruments; IO Leakage Current(nA): 1; USB High Speed: TRUE; IO Capacitance(Typ)(pF): 1.6; Eco-Plan: Green (RoHS & no Sb/Br); IEC 61000-4-2 Contact(+/- kV): 8; Breakdown Voltage(Min)(V): 6; IEC 61000-4-2 Air-Gap(+/- kV): 12; AEC Category: Q200; AEC Qualified: N; CompType: IC; SizeAreaWB_mm2: 4.9; SizeArea_mm2: 1.45; SizeX_mm: 1.0; SizeZ_mm: 0.6; Rating: Catalog
U4 = CMP-0089204-1: CPU16 MSP430™ FRAM Microcontroller IC 16-Bit 24MHz 32KB (32K x 8) FRAM 48-LQFP (7x7); Manufacturer: Texas Instruments; Memory Type: OTHER; Data Bus Width: 16bits; Number Of Spi Channels: 4; Number Of I/Os: 44; Number Of Uart Channels: 2; AEC Qualified: No; Standoff Height: 0.05mm; Ram Size: 4KBytes; TaMin_C: -40°C; Core Architecture: RISC; Number Of Adc Channels: 12; SizeZ_mm: 1.6mm; Number Of A/D Converters: 1; Memory Size: 32KBytes; TaMax_C: +105°C; TJmax_C: +115°C; Interface: I2C,SPI,UART,USART,SCI,IrDA; Min Supply Voltage: 1.8V; Max Supply Voltage: 3.6V
Y1 = CMP-0084387-1: Resonator, 4 MHz, 39 pF, AEC-Q200 Grade 1, SMD; Manufacturer: MuRata; Load Capacitance: 39 pF; AEC Qualified: Y; TaMax_C: 125°C; AEC Category: Q200; SizeArea_mm2: 9; SizeZ_mm: 1.2; Frequency_Fixed: 4MHz; SizeAreaWB_mm2: 16.5; SizeY_mm: 2; SizeX_mm: 4.5; TaMin_C: -40°C; AEC Grade: 1

## Sheet MD079_POWER_AND_CONNECTORS.SchDoc
size 431 x 279 mm; Date: Not shown in title block; ApprovedBy: Not shown in title block; CheckedBy: Not shown in title block; Author: Not shown in title block; CompanyName: Not shown in title block; Engineer: Not shown in title block; Organization: Not shown in title block; Address1: Not shown in title block; Address2: Not shown in title block; Address3: Not shown in title block; Address4: Not shown in title block; DocumentNumber: 5; Revision: Use project parameter SCH_Rev; SheetNumber: 4; SheetTotal: 5; PageSetup: Record=PageOptions¦CenterHorizontal=True¦CenterVertical=True¦PrintScale=1.00¦XCorrection=1.00¦YCorrection=1.00¦PrintKind=0¦BorderSize=5000000¦LeftOffset=0¦BottomOffset=0¦Orientation=2¦PaperLength=1000¦PaperWidth=1000¦Scale=100¦PaperSource=15¦PrintQuality=600¦MediaType=1¦DitherType=10¦PaperKind=Letter¦PrintScaleMode=1
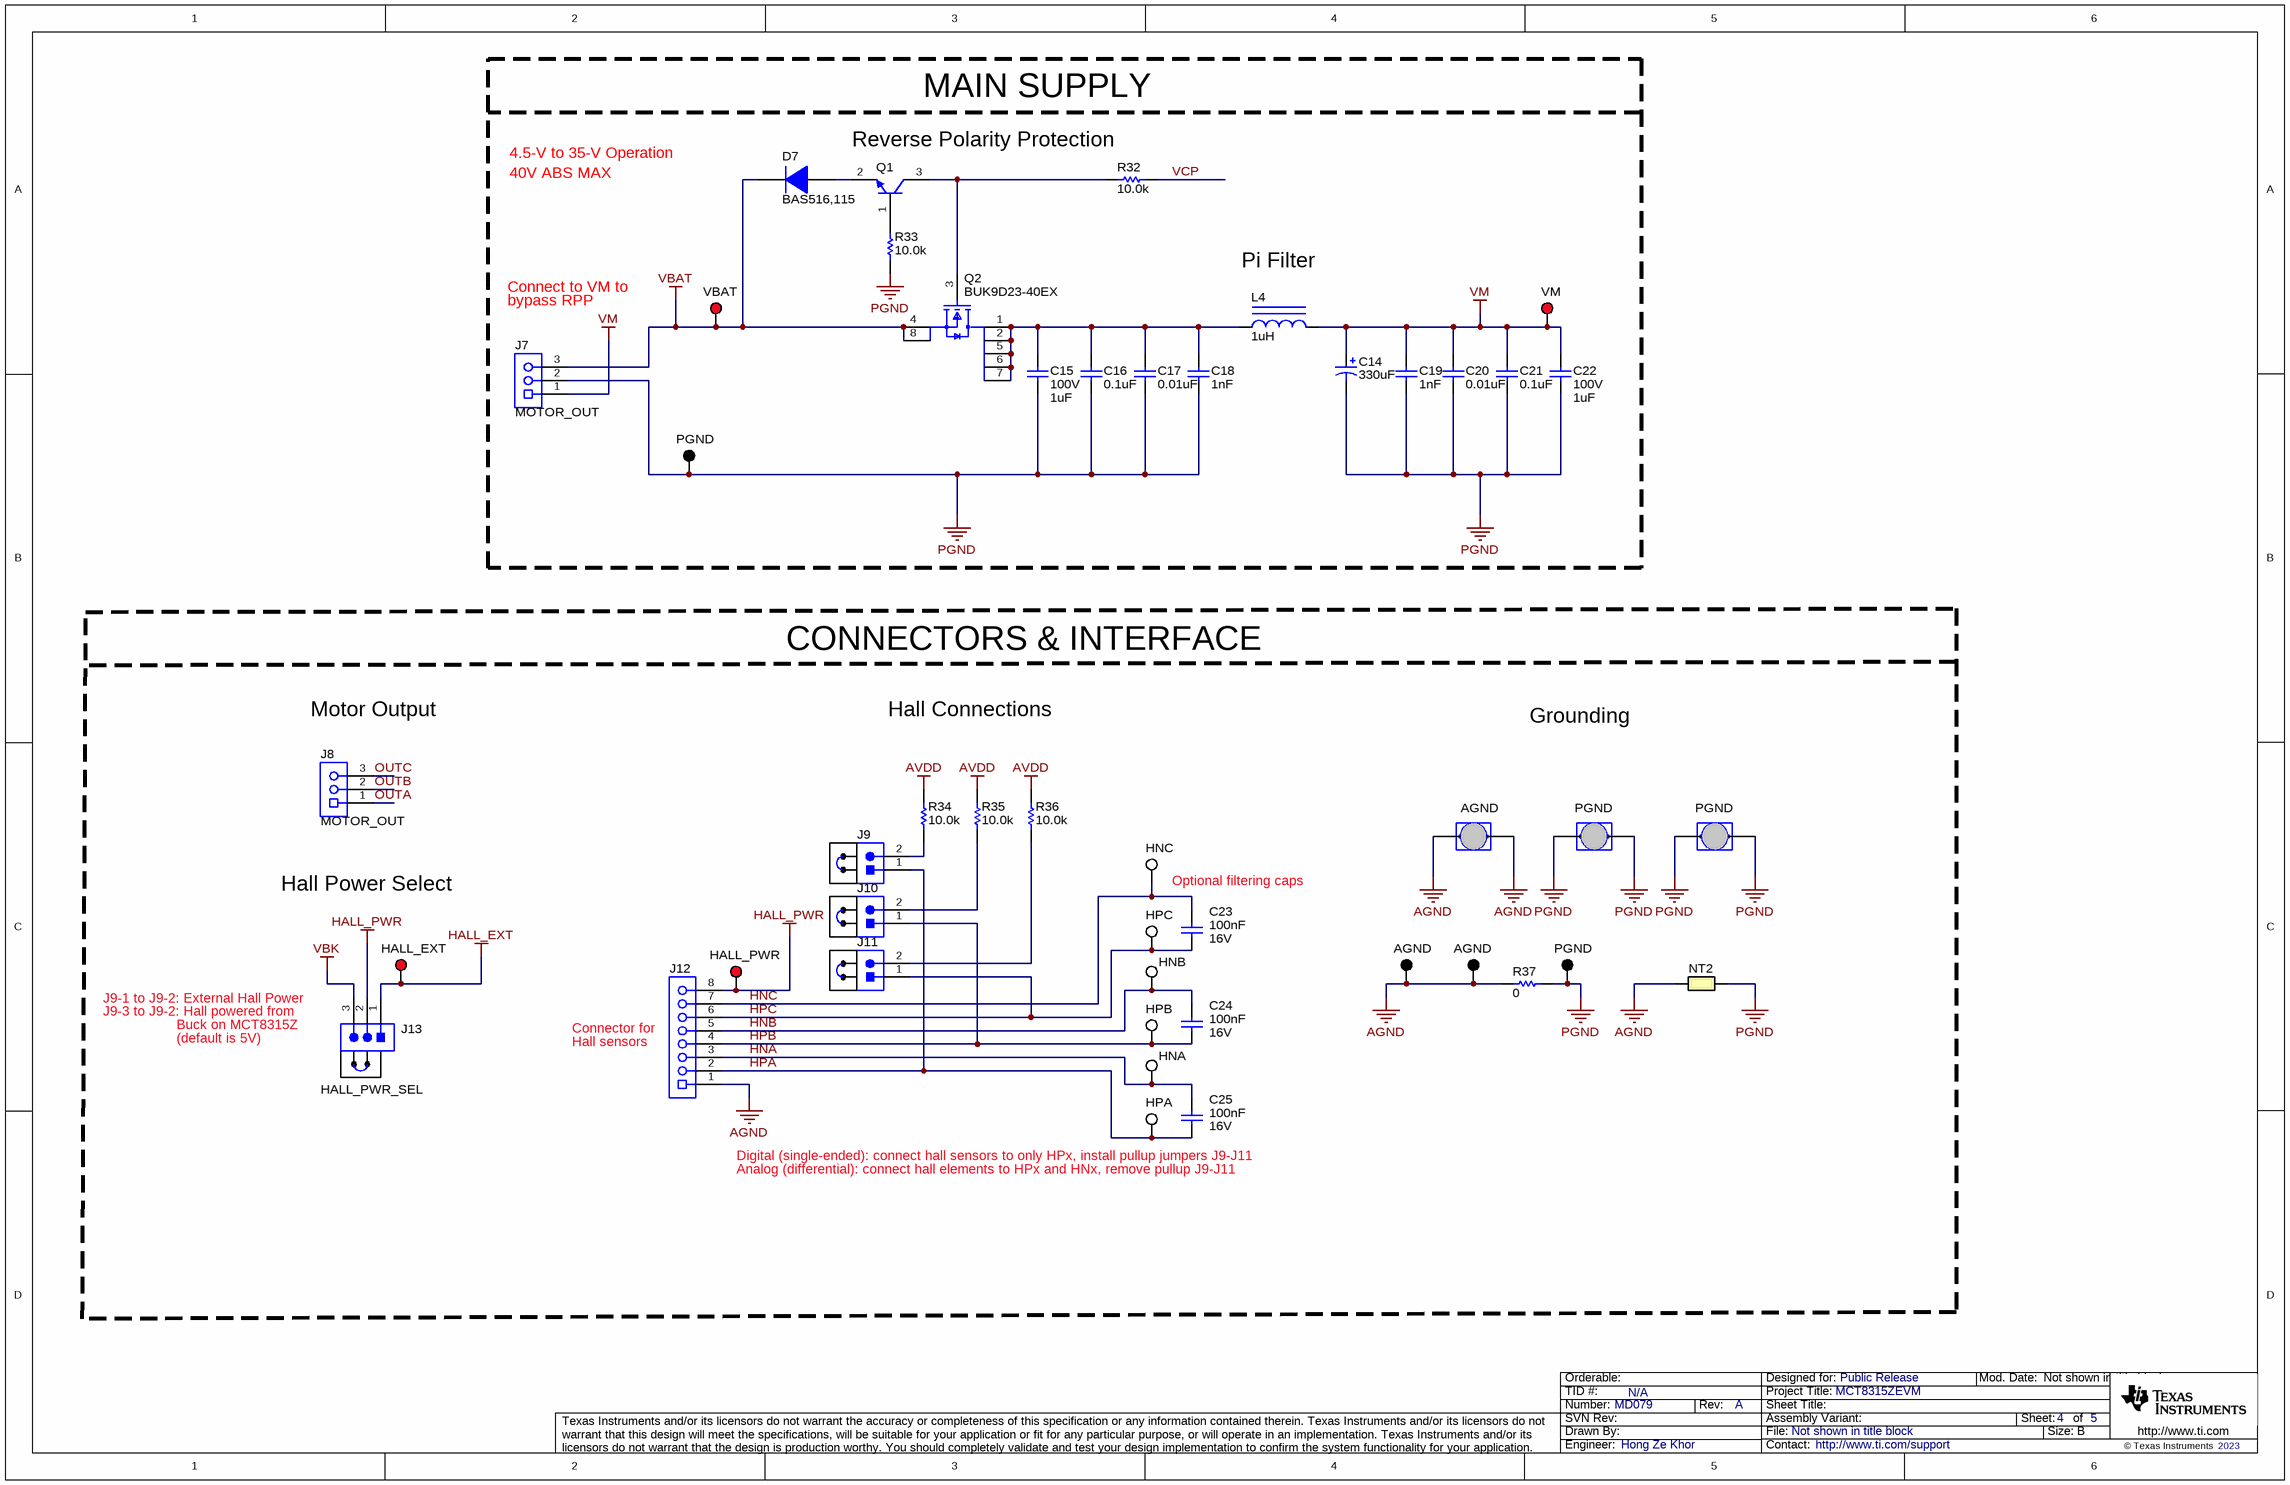
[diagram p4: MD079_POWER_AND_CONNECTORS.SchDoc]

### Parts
C14  ValueDisplayed: 330uF  [Chemi-Con_1250x2000]  (hidden comment: ELXZ630ELL331MK20S)
C15  VDC_V: 100V  ValueDisplayed: 1uF  [1206_180]  (hidden comment: GRM31CR72A105KA01L)
C16  ValueDisplayed: 0.1uF  [0603L]  (hidden comment: CGA3E3X7S2A104K080AB)
C17  ValueDisplayed: 0.01uF  [0603L]  (hidden comment: CGA3E2X7R2A103K080AA)
C18  Cap_F: 1nF  [0603L]  (hidden comment: 06031C102JAT2A)
C19  Cap_F: 1nF  [0603L]  (hidden comment: 06031C102JAT2A)
C20  ValueDisplayed: 0.01uF  [0603L]  (hidden comment: CGA3E2X7R2A103K080AA)
C21  ValueDisplayed: 0.1uF  [0603L]  (hidden comment: CGA3E3X7S2A104K080AB)
C22  VDC_V: 100V  ValueDisplayed: 1uF  [1206_180]  (hidden comment: GRM31CR72A105KA01L)
C23  Cap_F: 100nF  VDC_V: 16V  [0603L]  (hidden comment: 0603YC104K4T4A)
C24  Cap_F: 100nF  VDC_V: 16V  [0603L]  (hidden comment: 0603YC104K4T4A)
C25  Cap_F: 100nF  VDC_V: 16V  [0603L]  (hidden comment: 0603YC104K4T4A)
D7  BAS516,115  [SOD-523]
J7  MOTOR_OUT  [On-Shore_ED120_3DS]
J8  MOTOR_OUT  [On-Shore_ED120_3DS]
J9  PEC02SAAN  [CONN_PEC02SAAN]  (value not drawn)
J10  PEC02SAAN  [CONN_PEC02SAAN]  (value not drawn)
J11  PEC02SAAN  [CONN_PEC02SAAN]  (value not drawn)
J12  OSTTE080161  [On-Shore_OSTTE080161]  (value not drawn)
J13  HALL_PWR_SEL  [PBC03SAAN]
L4  ValueDisplayed: 1uH  [SRP1038A]  (hidden comment: SRP1038A-1R0M)
NT2  Net-Tie  [Net-Tie_50milWide_30milLong]  (value not drawn)  (net tie, no BOM)
Q1  FMMT620TA  [SOT-23L]  (value not drawn)
Q2  BUK9D23-40EX  [FP-BUK9D23-40EX_SOT1220-MFG]
R32  ValueDisplayed: 10.0k  [0603]  (hidden comment: RC0603FR-0710KL)
R33  ValueDisplayed: 10.0k  [0603]  (hidden comment: RC0603FR-0710KL)
R34  ValueDisplayed: 10.0k  [0603]  (hidden comment: RC0603FR-0710KL)
R35  ValueDisplayed: 10.0k  [0603]  (hidden comment: RC0603FR-0710KL)
R36  ValueDisplayed: 10.0k  [0603]  (hidden comment: RC0603FR-0710KL)
R37  ValueDisplayed: 0  [1206L]  (hidden comment: RCA12060000ZSEA)
SH-J13  SNT-100-BK-G  [SNT-100-BK-G]  (value not drawn)
SH-J14  SNT-100-BK-G  [SNT-100-BK-G]  (value not drawn)
SH-J15  SNT-100-BK-G  [SNT-100-BK-G]  (value not drawn)
SH-J16  SNT-100-BK-G  [SNT-100-BK-G]  (value not drawn)
TP15  VBAT  [Keystone5005]
TP16  VM  [Keystone5005]
TP17  PGND  [Keystone5001]
TP18  AGND  [Harwin_D3082-05]
TP19  PGND  [Harwin_D3082-05]
TP20  PGND  [Harwin_D3082-05]
TP21  HNC  [Keystone5002]
TP22  HPC  [Keystone5002]
TP23  HALL_EXT  [Keystone5000]
TP24  AGND  [Keystone5001]
TP25  AGND  [Keystone5001]
TP26  PGND  [Keystone5001]
TP27  HALL_PWR  [Keystone5000]
TP28  HNB  [Keystone5002]
TP29  HPB  [Keystone5002]
TP30  HNA  [Keystone5002]
TP31  HPA  [Keystone5002]

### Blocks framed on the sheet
MAIN SUPPLY: C14-C22 D7 J7 L4 Q1 Q2 R32 R33 TP15-TP17

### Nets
AGND: J12.1 NT2.1 R37.1 TP18.1 TP18.2 TP24.1 TP25.1
AVDD: R34.1 R35.1 R36.1
HALL_EXT: J13.1 TP23.1
HALL_PWR: J12.8 J13.2 TP27.1
PGND: C14.2(-) C15.2 C16.2 C17.2 C18.2 C19.2 C20.2 C21.2 C22.2 J7.2 NT2.2 R33.1 R37.2 TP17.1 TP19.1 TP19.2 TP20.1 TP20.2 TP26.1
VBAT: D7.1(K) J7.3 Q2.4(S) Q2.8(S) TP15.1
VBK: J13.3
VM: C14.1(+) C19.1 C20.1 C21.1 C22.1 J7.1 L4.2 TP16.1
HNA: C25.1 J12.3 TP30.1
HNB: C24.1 J12.5 TP28.1
HNC: C23.1 J12.7 TP21.1
HPA: C25.2 J9.1 J12.2 TP31.1
HPB: C24.2 J10.1 J12.4 TP29.1
HPC: C23.2 J11.1 J12.6 TP22.1
OUTA: J8.1
OUTB: J8.2
OUTC: J8.3
VCP: R32.1
NetC15_1: C15.1 C16.1 C17.1 C18.1 L4.1 Q2.1(D) Q2.2(D) Q2.5(D) Q2.6(D) Q2.7(D)
NetD7_2: D7.2(A) Q1.2(E)
NetJ9_2: J9.2 R34.2
NetJ10_2: J10.2 R35.2
NetJ11_2: J11.2 R36.2
NetQ1_1: Q1.1(B) R33.2
NetQ1_3: Q1.3(C) Q2.3(G) R32.2

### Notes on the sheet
- 40V ABS MAX
- 4.5-V to 35-V Operation
- Reverse Polarity Protection
- bypass RPP
- Connect to VM to
- Pi Filter
- CONNECTORS & INTERFACE
- Motor Output
- Hall Connections
- Grounding
- Hall Power Select
- Optional filtering caps
- (near J13) J9-1 to J9-2: External Hall Power
- J9-3 to J9-2: Hall powered from
- Buck on MCT8315Z
- (near J12) Connector for
- (default is 5V)
- (near J12) Hall sensors
- Digital (single-ended): connect hall sensors to only HPx, install pullup jumpers J9-J11
- Analog (differential): connect hall elements to HPx and HNx, remove pullup J9-J11

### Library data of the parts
C14 = CMP-0009912-2: CAP, AL, 330 uF, 63 V, +/- 20%, AEC-Q200 Grade 2, TH; Manufacturer: Chemi-Con; Polarized: Y; CompType: Capacitor; Value: 330uF; U/M: EA; Cap_F: 330µF; Value1: Unknown; VDC_V: 63V; IRMS_A: 1.29A; TaMin_C: -55°C; TaMax_C: 105°C; Cap_Case: 12.5x20mm; AEC Category: Q200; AEC Grade: 2; SizeAreaWB_mm2: 210.25; SizeArea_mm2: 156.25; SizeX_mm: 12.5; SizeZ_mm: 21.5
C15 C22 = CMP-0008970-2: CAP, CERM, 1 uF, 100 V, +/- 10%, X7R, 1206; Manufacturer: MuRata; TaMin_C: -55°C; Polarized: N; SizeAreaWB_mm2: 10.92; Value1: Unknown; U/M: EA; Value: 1uF; TaMax_C: 125°C; SizeZ_mm: 1.8; SizeX_mm: 3.2; SizeY_mm: 1.6; Cap_Case: 2220; SizeArea_mm2: 5.12; Cap_F: 1µF; AEC Category: Q200
C16 C21 = CMP-0007099-4: CAP, CERM, 0.1 uF, 100 V, +/- 10%, X7S, AEC-Q200 Grade 1, 0603; Manufacturer: TDK; Polarized: N; Value: 0.1uF; U/M: EA; Cap_F: 100nF; ESR_ohm: 0.04959; Value1: 0.04959 ohm; VDC_V: 100V; IRMS_A: 751.618mA; TaMin_C: -55°C; TaMax_C: 125°C; Cap_Case: 0603; AEC Category: Q200; AEC Qualified: Y; AEC Grade: 1; SizeAreaWB_mm2: 4.68; SizeX_mm: 1.6; SizeY_mm: 0.8; SizeArea_mm2: 1.28
C17 C20 = CMP-0007082-4: CAP, CERM, 0.01 uF, 100 V, +/- 10%, X7R, AEC-Q200 Grade 1, 0603; Manufacturer: TDK; Polarized: N; Value: 0.01uF; U/M: EA; Cap_F: 10nF; ESR_ohm: 0.235428; Value1: 0.235428 ohm; VDC_V: 100V; IRMS_A: 396.995mA; TaMin_C: -55°C; TaMax_C: 125°C; Cap_Case: 0603; AEC Category: Q200; AEC Qualified: Y; AEC Grade: 1; SizeArea_mm2: 1.28; SizeAreaWB_mm2: 4.68; SizeX_mm: 1.6; SizeY_mm: 0.8
C18 C19 = CMP-0006723-4: CAP, CERM, 1000 pF, 100 V, +/- 5%, X7R, 0603; Manufacturer: AVX; TaMin_C: -55°C; ESR_ohm: 2.76d; Polarized: N; SizeAreaWB_mm2: 4.68; Value1: 0.276 ohm; U/M: EA; Value: 1000pF; TaMax_C: 125°C; SizeZ_mm: 1; SizeX_mm: 1.6; SizeY_mm: 0.8; Cap_Case: 0603; Value2: 100V; SizeArea_mm2: 1.28; AEC Category: Q200
C23-C25 = CMP-0083626-1: CAP, CERM, 0.1 µF, 16 V,+/- 10%, X7R, AEC-Q200 Grade 1, 0603; Manufacturer: AVX; SizeAreaWB_mm2: 4.68; SizeArea_mm2: 1.28; AEC Qualified: Y; AEC Category: Q200; Value: 0.1uF; TaMax_C: 125°C; SizeZ_mm: 1; Polarized: N; TaMin_C: -55°C; SizeY_mm: 0.8; U/M: EA; SizeX_mm: 1.6; Cap_Case: 0603; ValueDisplayed: 0.1µF
D7 = CMP-0076979-3: Diode, Switching, 100 V, 0.25 A, SOD-523; Manufacturer: Nexperia; Value: 100V; SizeAreaWB_mm2: 5.13; Vf_V: 1.25V; SizeArea_mm2: 1.53; SizeY_mm: 0.9; Green_Lifecycle: Not Set; AEC Category: Q101; SizeX_mm: 1.7; Green_REACh: Incomplete; Io_A: 250mA; TJmax_C: 150°C; SizeZ_mm: 0.65; Value1: 0.25A
J7 J8 = CMP-0074911-1: Terminal Block, 5.08 mm, 3x1, Brass, TH; Manufacturer: On-Shore Technology; PartNumber: ED120/3DS; Cert_VDE: Y; CNHeader: False; Current_A: 15A; Green_Lifecycle: Not Set; Shrouded: N; Gender: Female; Green_REACh: Incomplete; Voltage_V: 300V; Row_Count: 1; Pitch_mm: 5.08; CT: True
J9-J11 = CMP-0002337-1: Header, 100mil, 2x1, Tin, TH; Manufacturer: Sullins Connector Solutions; CNHeader: TRUE; Current_A: 3A; Green_Lifecycle: Not Set; Shrouded: N; Gender: Male; Green_REACh: Incomplete; Voltage_V: 1.8kV; Row_Count: 1; Pitch_mm: 2.54; CT: FALSE; Cert_UL: Y
J12 = CMP-0074957-2: Terminal Block, 8x1, 3.5mm, TH; Manufacturer: On-Shore Technology; CT: True; Green_REACh: Incomplete; CNHeader: False; Green_Lifecycle: Not Set
J13 = CMP-0002334-1: as J1 on sheet MD079_CONTROL
L4 = CMP-0056795-1: Inductor, Shielded, Powdered Iron, 1 uH, 18 A, 0.003 ohm, AEC-Q200 Grade 1, SMD; Manufacturer: Bourns; Isat: 36A @ 20% inductance drop; Irms: 18A @ 40C rise; Green_Lifecycle: Active; SizeAreaWB_mm2: 156; DCR_ohm: 3m; Green_REACh: Passed; Value: 1uH; Imax_A: 18A; SizeZ_mm: 4; SizeX_mm: 11; SizeY_mm: 10; SizeArea_mm2: 110; Ind_H: 1µH; AEC Qualified: Y; AEC Grade: 1; AEC Category: Q200
NT2 = CMP-0078142-6: Single point connection between nets.
Q1 = CMP-0000467-2: Transistor, NPN, 80 V, 1.5 A, AEC-Q101, SOT-23; Manufacturer: Diodes Inc.; TaMax_C: 150°C; Value2: 900; Value1: 1.5 A; Vcesat1_V: 160mV; SizeX_mm: 2.5; SizeY_mm: 3; TaMin_C: -55°C; IcRated_A: 1.5A; CompType: BJT; SizeZ_mm: 1.1; AEC Qualified: Y; Value: 80 V; SizeArea_mm2: 7.5; NPN: 1; Vceo_V: 80V; PNP: 0; AEC Category: Q101; SizeAreaWB_mm2: 14; U/M: EA
Q2 = CMP-0088880-1: N-Channel 40V 8A (Ta) 15W (Tc) Surface Mount DFN2020MD-6; Manufacturer: Nexperia; Reverse Recovery Charge: 5.3nC; Vgs_V: 15V; Rthja Max: 57K/W; Number Of N Channels: 1; Pulse Drain Current: 76A; Threshold Vgs Max: 2.1V; Power_W: 2.3W; Reverse Recovery Time: 12.9ns; TaMin_C: -55°C; Rdson45_ohm: 0.018; SizeZ_mm: 0.65mm; ChMode: False; Transconductance: 39S; AEC Qualified: Yes; Typ Forward Diode Voltage: 0.8V; Turn Off Delay Time: 12ns; TaMax_C: +175°C; Input Capacitace At Vds: 637pF @ 20V; QgTyp_nC: 11.5nC @ 10V; Threshold Vgs Min: 1.4V; AEC Grade: Grade 0; VdsMax_V: 1.2V; Turn On Delay Time: 2ns
R32-R36 = CMP-0022746-5: as R1 on sheet MD079_CONTROL
R37 = CMP-0018760-2: RES, 0, 5%, 0.25 W, AEC-Q200 Grade 0, 1206; Manufacturer: Vishay-Dale; Power_W: 250mW; TempCo: ppm/C; Value_Code: 0000; U/M: EA; Value: 0; EIA_Code: E24; SizeX_mm: 3.2; SizeY_mm: 1.6; SizeZ_mm: 1.35; Value2: 0.25W; SizeArea_mm2: 5.12; AEC Qualified: Y; AEC Category: Q200
SH-J13-SH-J16 = CMP-0003623-3: as SH-J1 on sheet MD079_CONTROL
TP15 TP16 = CMP-0055142-2: Test Point, Compact, Red, TH; Manufacturer: Keystone Electronics; CNHeader: FALSE; ContactFinish: Silver; CT: TRUE; Green_Lifecycle: Active; Green_REACh: Passed
TP17 TP24-TP26 = CMP-0055138-2: Test Point, Miniature, Black, TH; Manufacturer: Keystone Electronics; CNHeader: FALSE; Green_Lifecycle: Active; Green_REACh: Passed; ContactFinish: Silver; CT: TRUE
TP18-TP20 = CMP-0075110-1: 1mm Uninsulated Shorting Plug, 10.16mm spacing, TH; Manufacturer: Harwin; PartNumber: D3082-05; CNHeader: False; Green_Lifecycle: Active; Green_REACh: Passed; CompType: Jumper Wire
TP21 TP22 TP28-TP31 = CMP-0055139-2: as TP1 on sheet MD079_CONTROL
TP23 TP27 = CMP-0055137-2: as TP6 on sheet MD079_DRIVER

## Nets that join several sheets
AGND: MD079_CONTROL (R5.3 R6.1 R7.1 R8.1), MD079_DRIVER (11 pins), MD079_INTERFACE (25 pins), MD079_POWER_AND_CONNECTORS (7 pins)
AVDD: MD079_CONTROL (R1.2 R2.2 R3.2 R5.1), MD079_DRIVER (9 pins), MD079_POWER_AND_CONNECTORS (R34.1 R35.1 R36.1)
PGND: MD079_DRIVER (5 pins), MD079_POWER_AND_CONNECTORS (19 pins)
VBK: MD079_DRIVER (7 pins), MD079_POWER_AND_CONNECTORS (J13.3)
VM: MD079_DRIVER (6 pins), MD079_POWER_AND_CONNECTORS (8 pins)
BRAKE: MD079_CONTROL (S1.2 TP3.1), MD079_DRIVER (U1.31)
CLK: MD079_DRIVER (R13.1), MD079_INTERFACE (J6.7)
DIR: MD079_CONTROL (S2.2 TP4.1), MD079_DRIVER (R17.1)
DRVOFF: MD079_CONTROL (S3.2 TP5.1), MD079_DRIVER (U1.15)
FGOUT: MD079_DRIVER (R9.1 TP11.1 U1.1), MD079_INTERFACE (J6.1)
HNA: MD079_DRIVER (U1.21), MD079_POWER_AND_CONNECTORS (C25.1 J12.3 TP30.1)
HNB: MD079_DRIVER (U1.23), MD079_POWER_AND_CONNECTORS (C24.1 J12.5 TP28.1)
HNC: MD079_DRIVER (U1.25), MD079_POWER_AND_CONNECTORS (C23.1 J12.7 TP21.1)
HPA: MD079_DRIVER (U1.20), MD079_POWER_AND_CONNECTORS (C25.2 J9.1 J12.2 TP31.1)
HPB: MD079_DRIVER (U1.22), MD079_POWER_AND_CONNECTORS (C24.2 J10.1 J12.4 TP29.1)
HPC: MD079_DRIVER (U1.24), MD079_POWER_AND_CONNECTORS (C23.2 J11.1 J12.6 TP22.1)
MSP_POT_P1.1: MD079_CONTROL (R4.1), MD079_INTERFACE (U4.2)
MSP_PWM_P2.0: MD079_CONTROL (J1.3 TP1.1), MD079_INTERFACE (U4.30)
nFAULT: MD079_DRIVER (R24.1 U1.16), MD079_INTERFACE (J6.13)
nSLEEP: MD079_DRIVER (U1.17), MD079_INTERFACE (J6.15)
OUTA: MD079_DRIVER (TP6.1 U1.11), MD079_POWER_AND_CONNECTORS (J8.1)
OUTB: MD079_DRIVER (TP9.1 U1.12), MD079_POWER_AND_CONNECTORS (J8.2)
OUTC: MD079_DRIVER (TP10.1 U1.13), MD079_POWER_AND_CONNECTORS (J8.3)
PWM: MD079_DRIVER (U1.32), MD079_INTERFACE (J6.3)
PWM_SEL: MD079_CONTROL (J1.2), MD079_INTERFACE (J6.4)
SIMO: MD079_DRIVER (R14.1), MD079_INTERFACE (J6.9)
SOMI: MD079_DRIVER (R12.1 R15.1), MD079_INTERFACE (J6.11)
STE: MD079_DRIVER (R16.1), MD079_INTERFACE (J6.5)
VCP: MD079_DRIVER (C1.1 U1.7), MD079_POWER_AND_CONNECTORS (R32.1)

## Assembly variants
001: not fitted C23 C24 C25 L2 R10 R17 R20 R21 R22 R26 R27 R28
002: not fitted C23 C24 C25 L2 R10 R13 R14 R15 R16 R20 R27 R28
003: not fitted C6 C23 C24 C25 D1 L1 L2 R10 R13 R14 R15 R16 R20 R23 R27 R28 TP7 TP8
